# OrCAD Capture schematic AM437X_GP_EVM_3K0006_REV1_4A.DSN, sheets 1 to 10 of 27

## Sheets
1 Pg15: Camera #1: size C; title: AM437x General Purpose EVM; rev: 1.4A; company: Texas Instruments; note: am437x_gp_evm_3k0006_rev1_4a.dsn; note: ARM MPU BU; note: Final
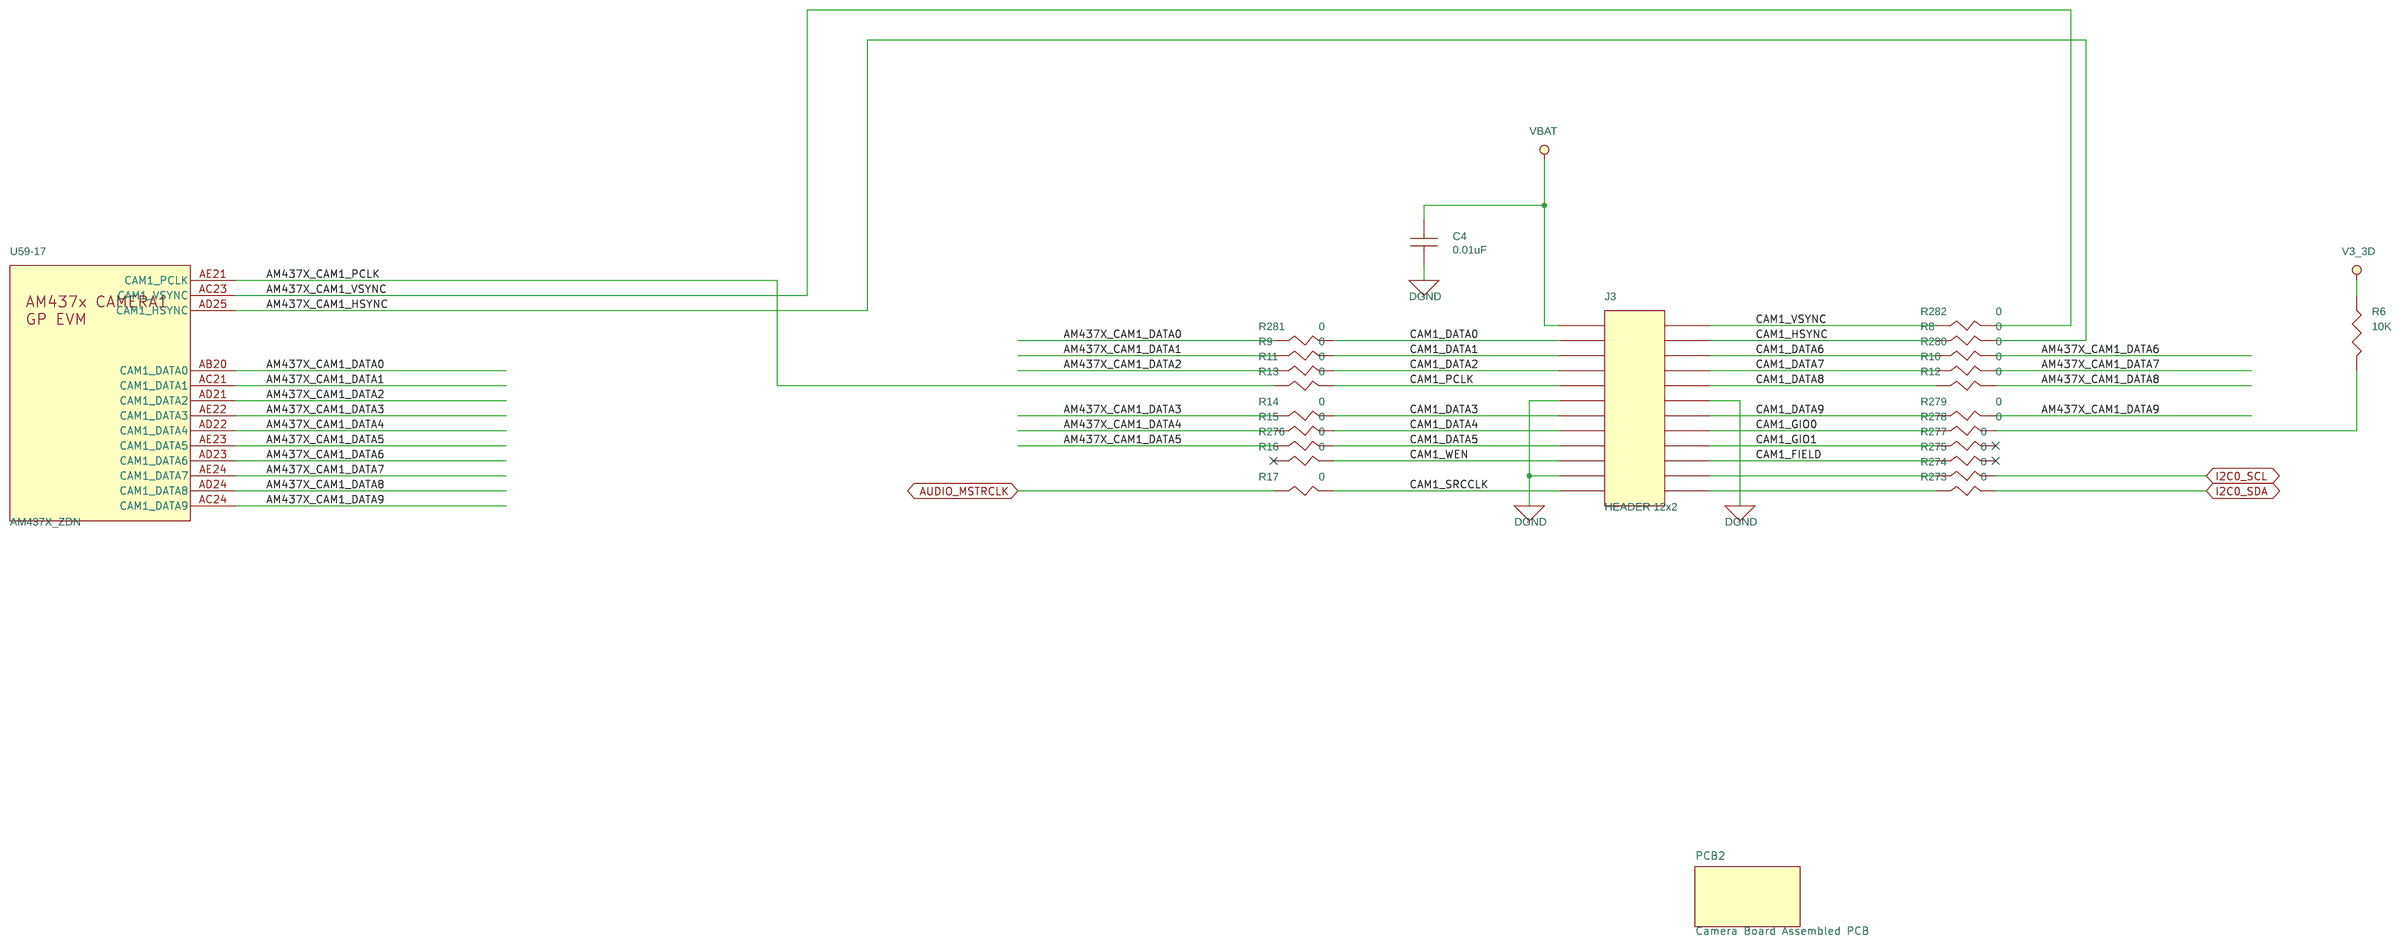
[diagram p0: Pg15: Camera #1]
2 Pg09: UART#0: size C
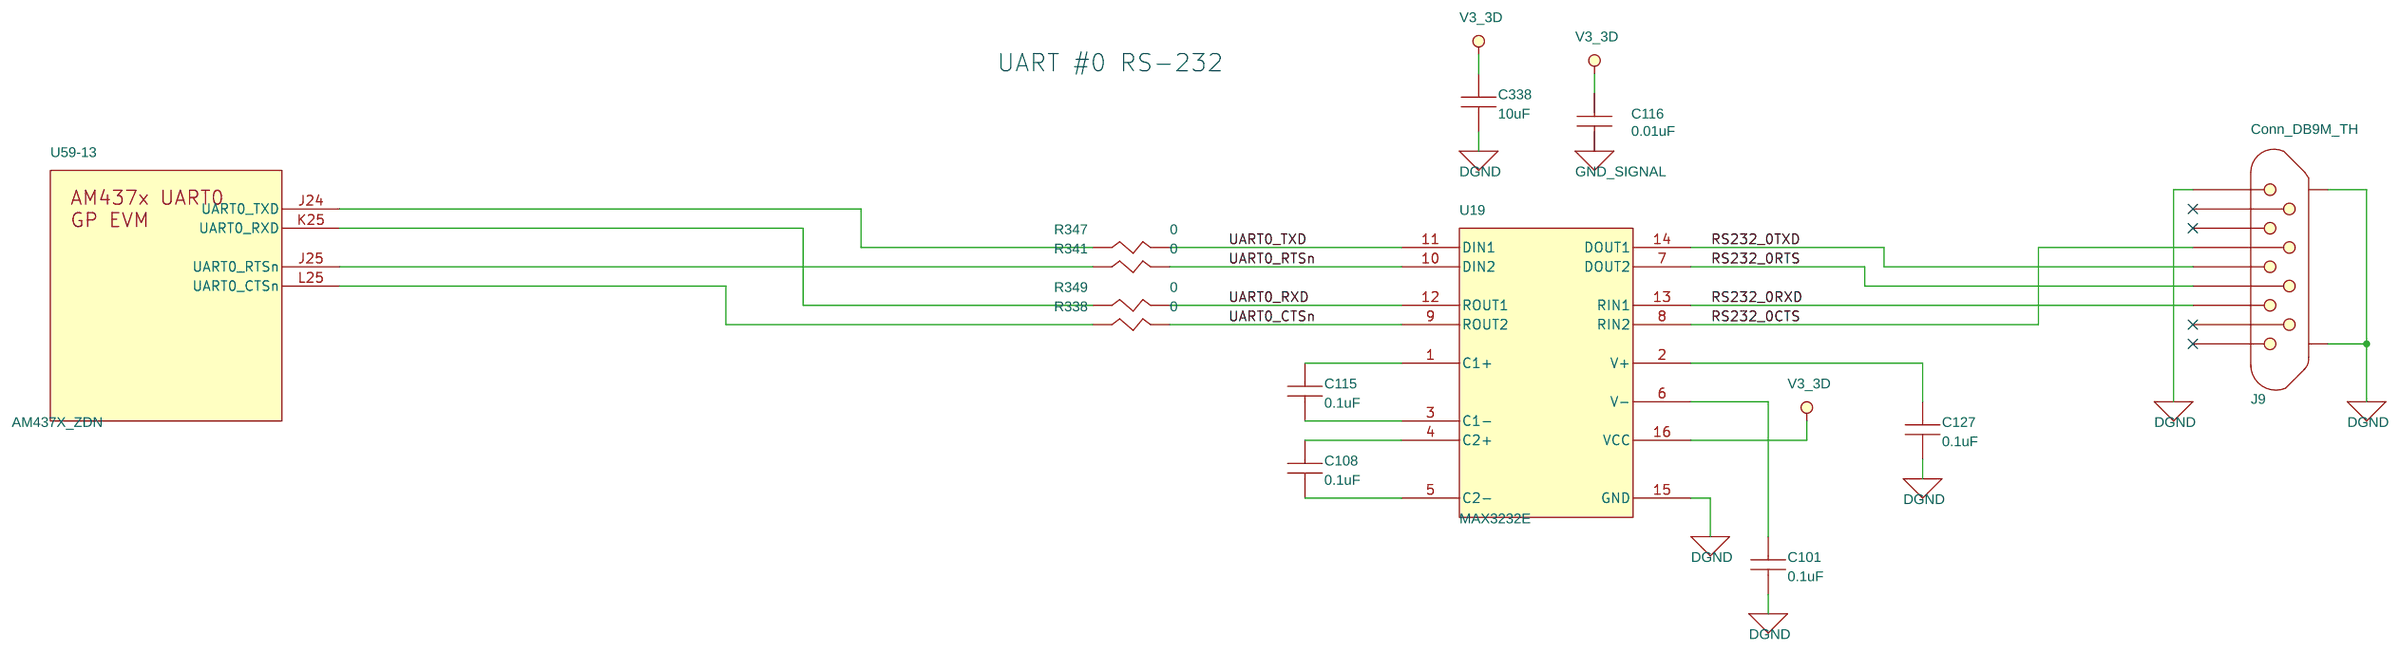
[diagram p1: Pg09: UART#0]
3 Pg13: HDMI: size C
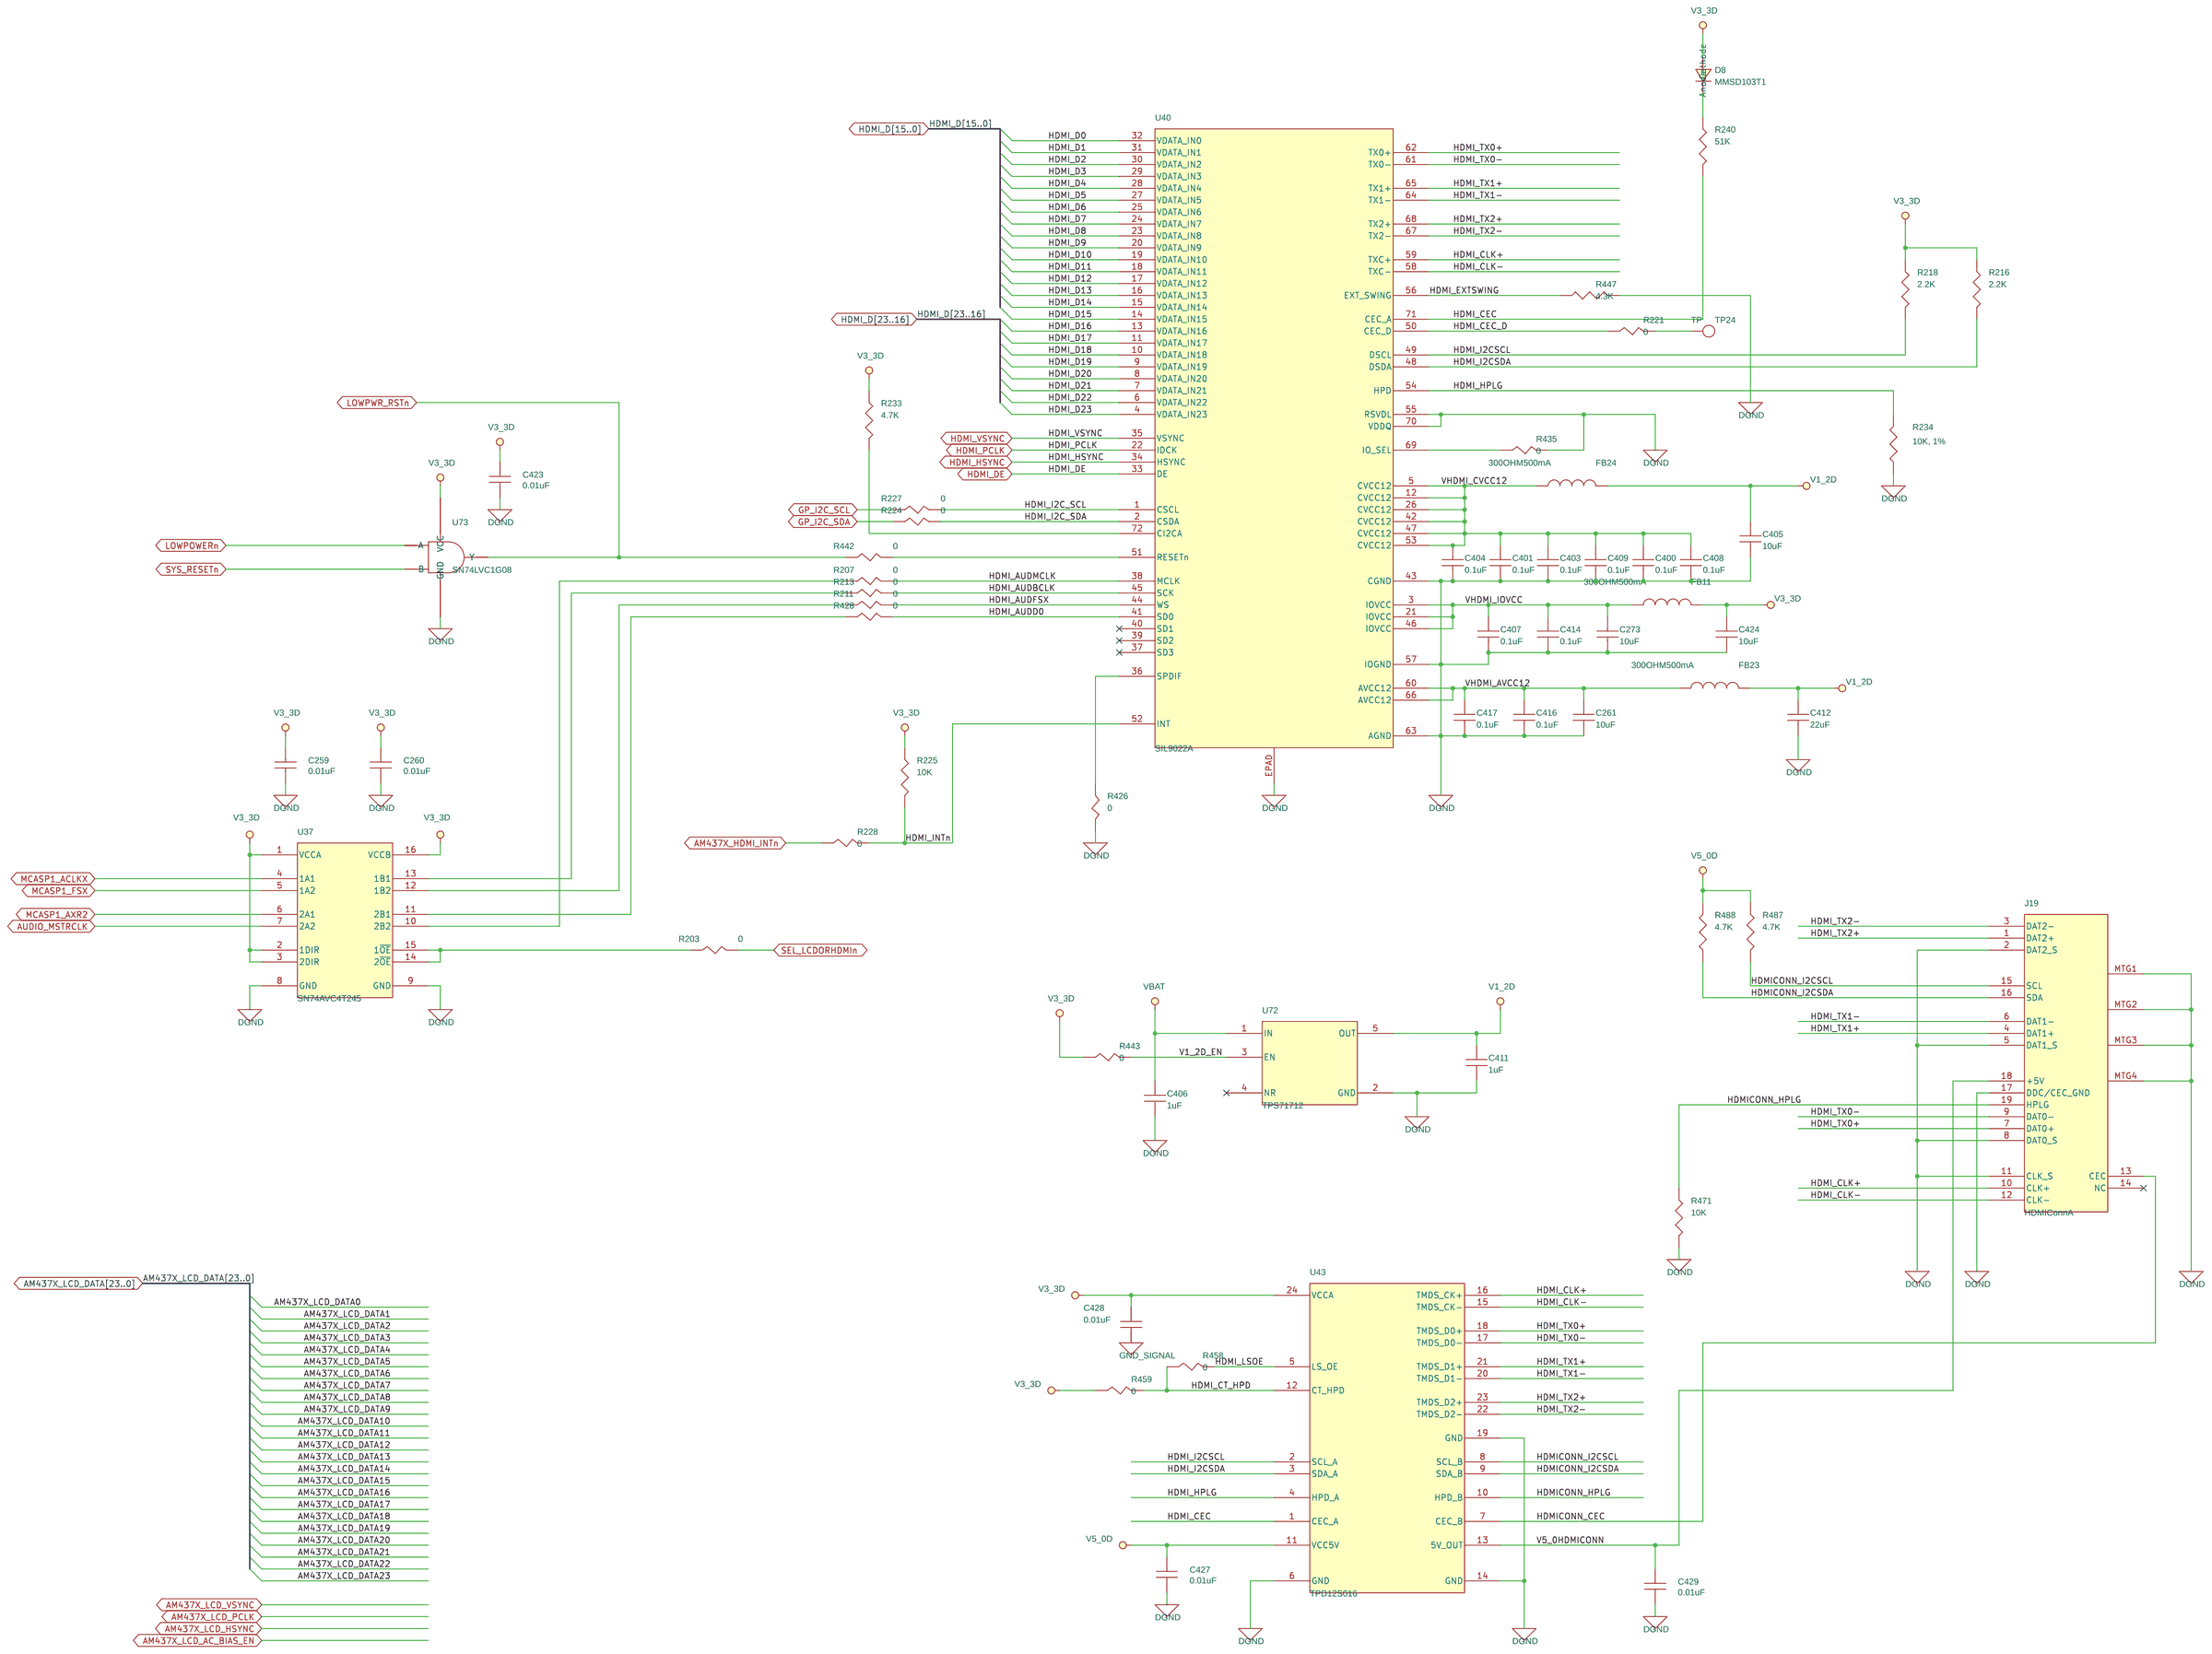
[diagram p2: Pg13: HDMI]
4 Pg16: ADC: size C
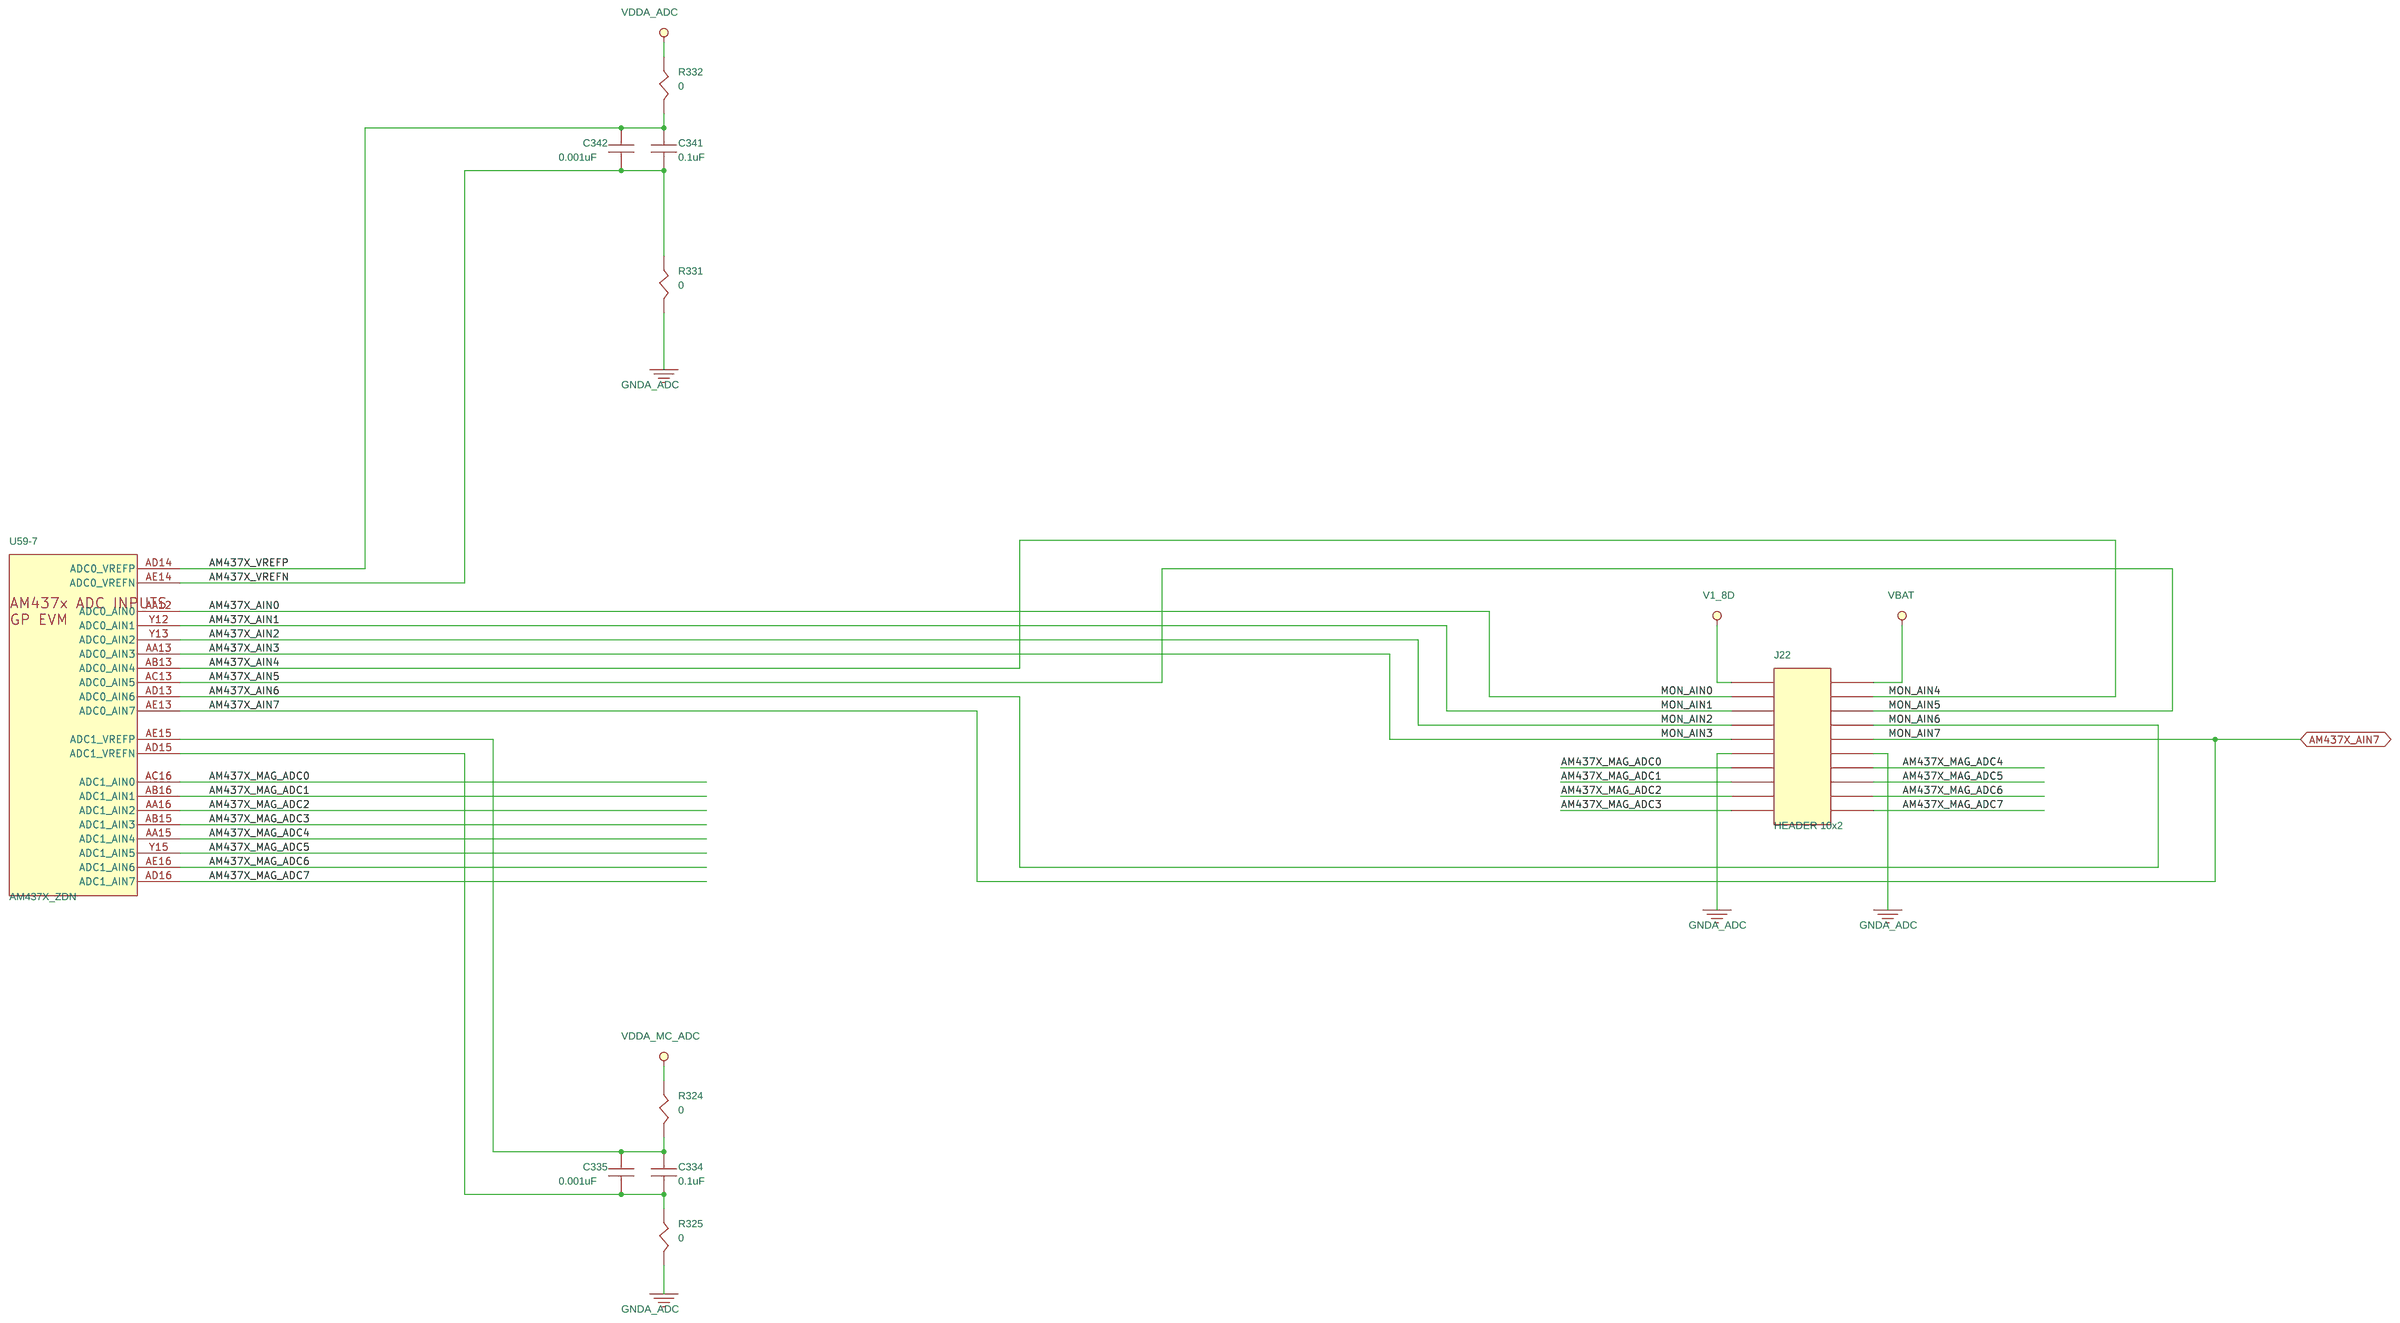
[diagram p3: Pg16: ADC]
5 Pg12: LCD: size C
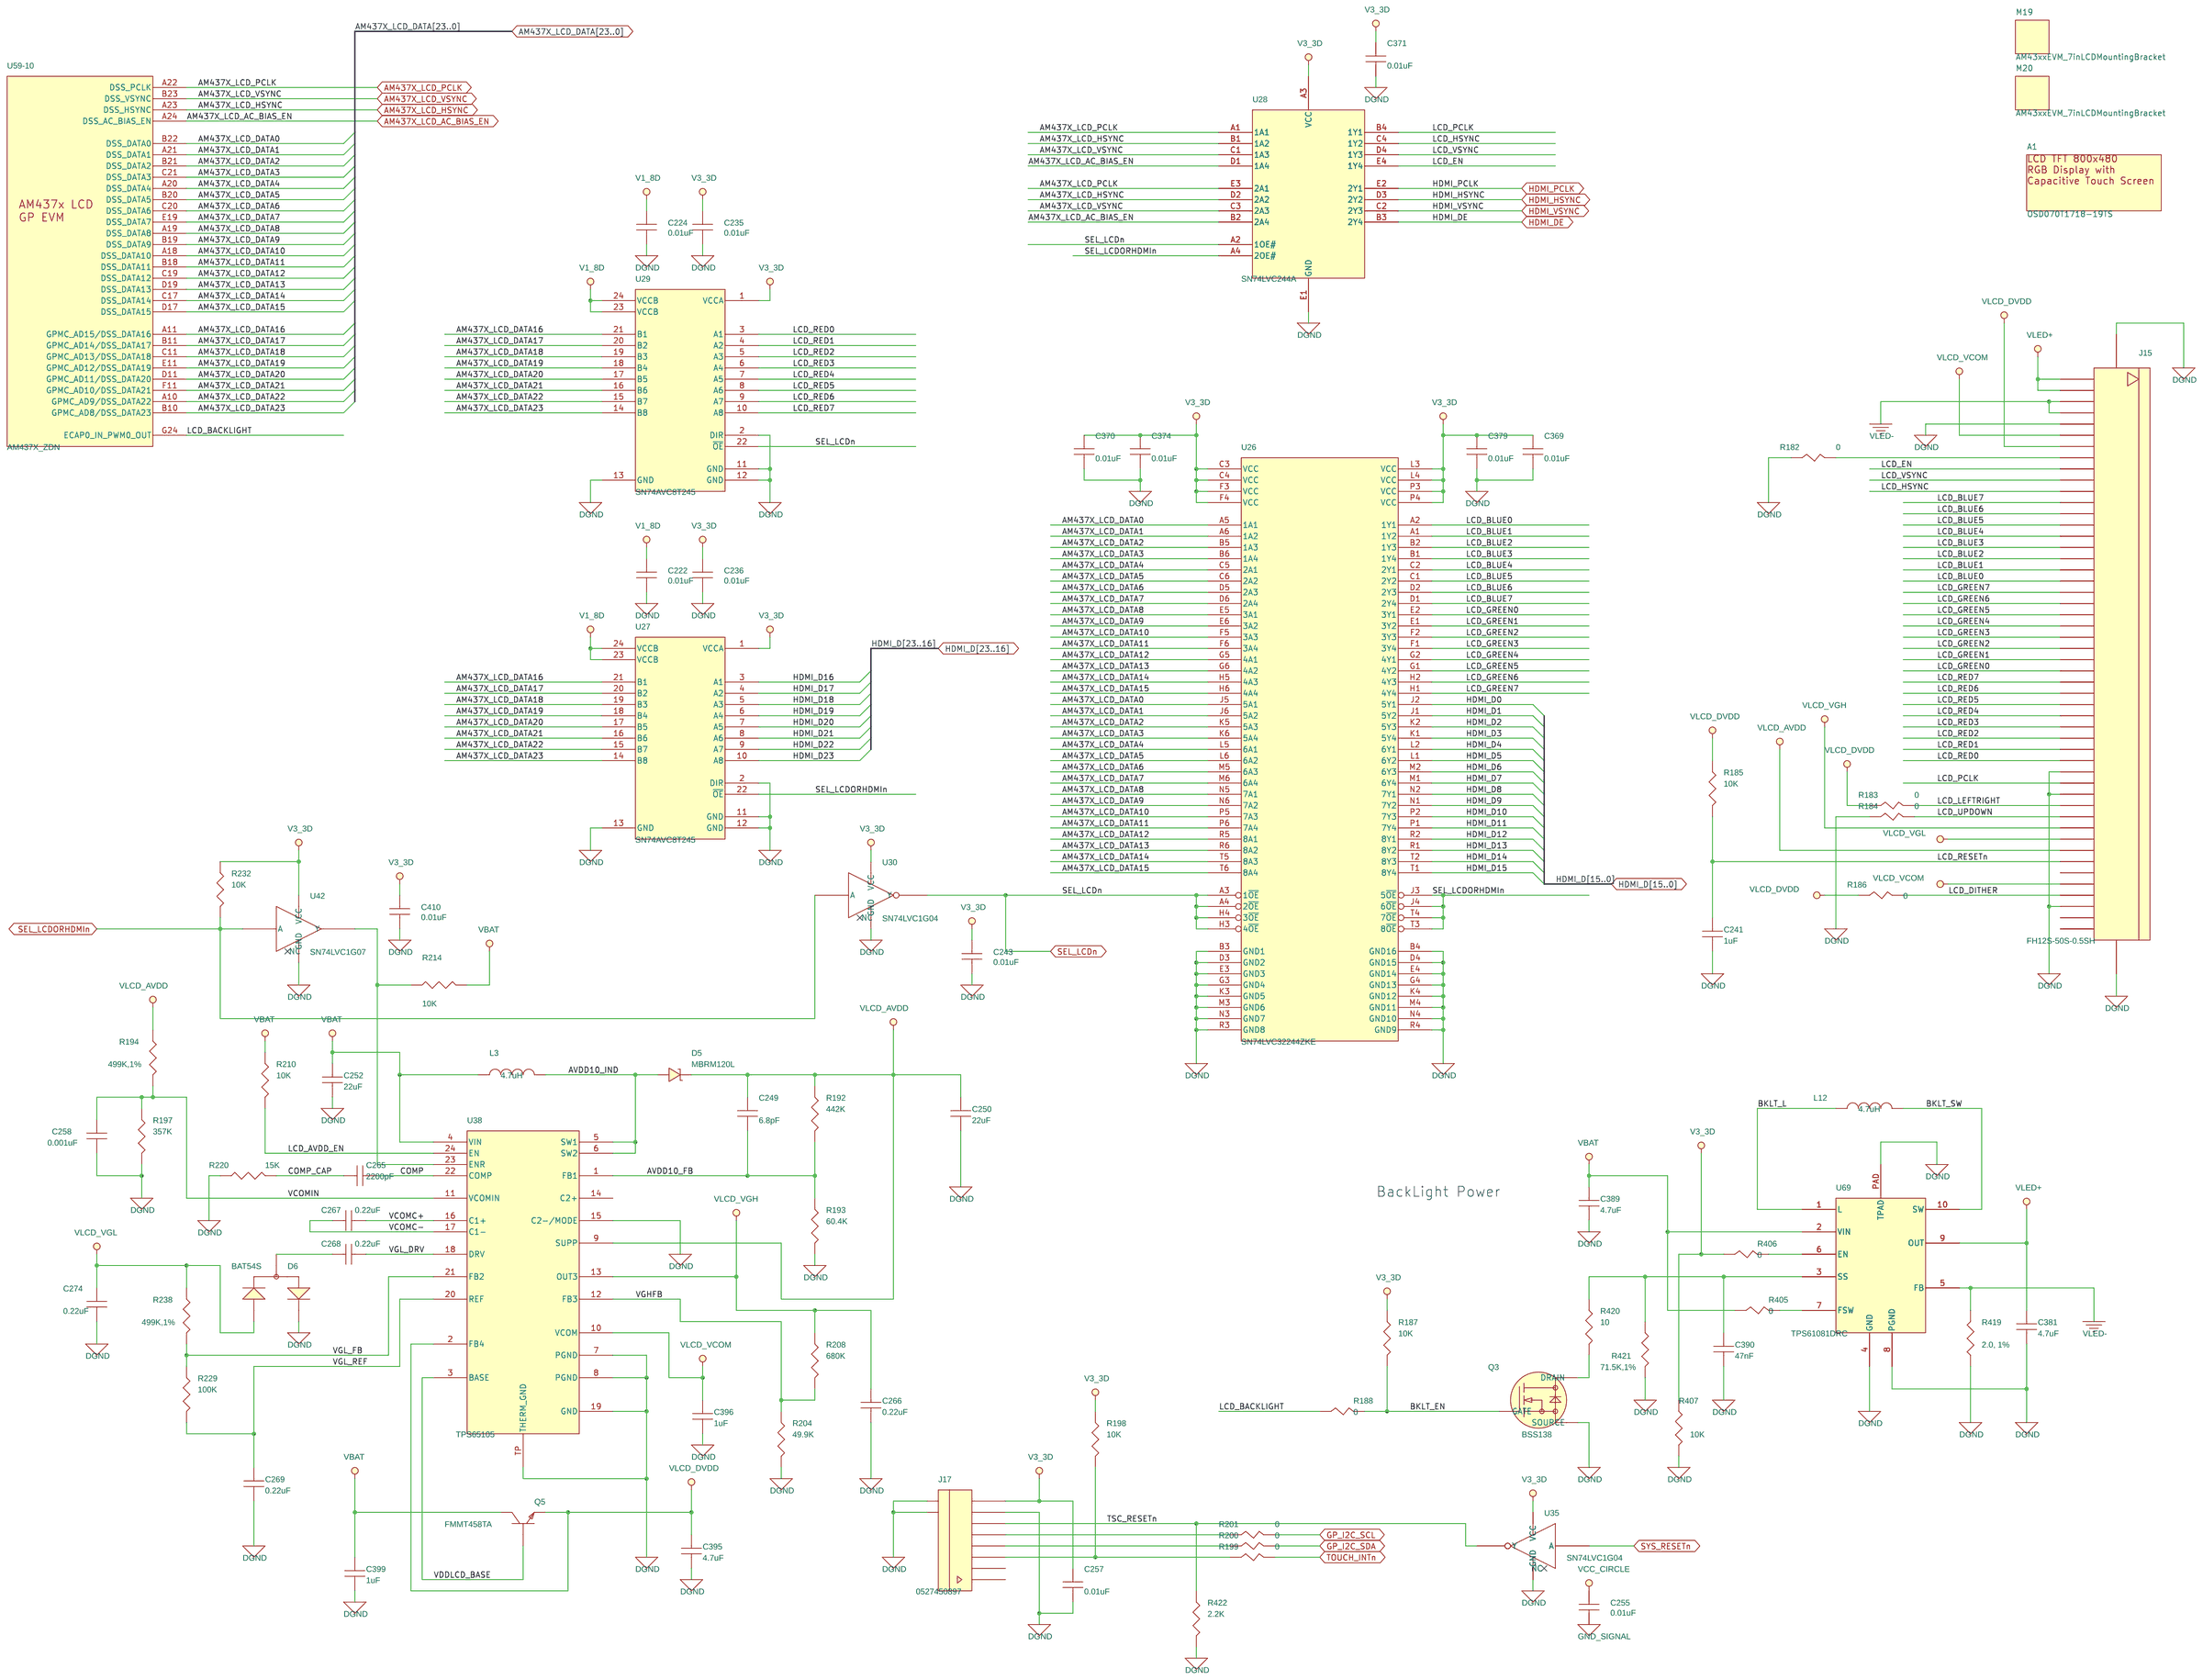
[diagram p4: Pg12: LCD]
6 Pg11: Audio: size C
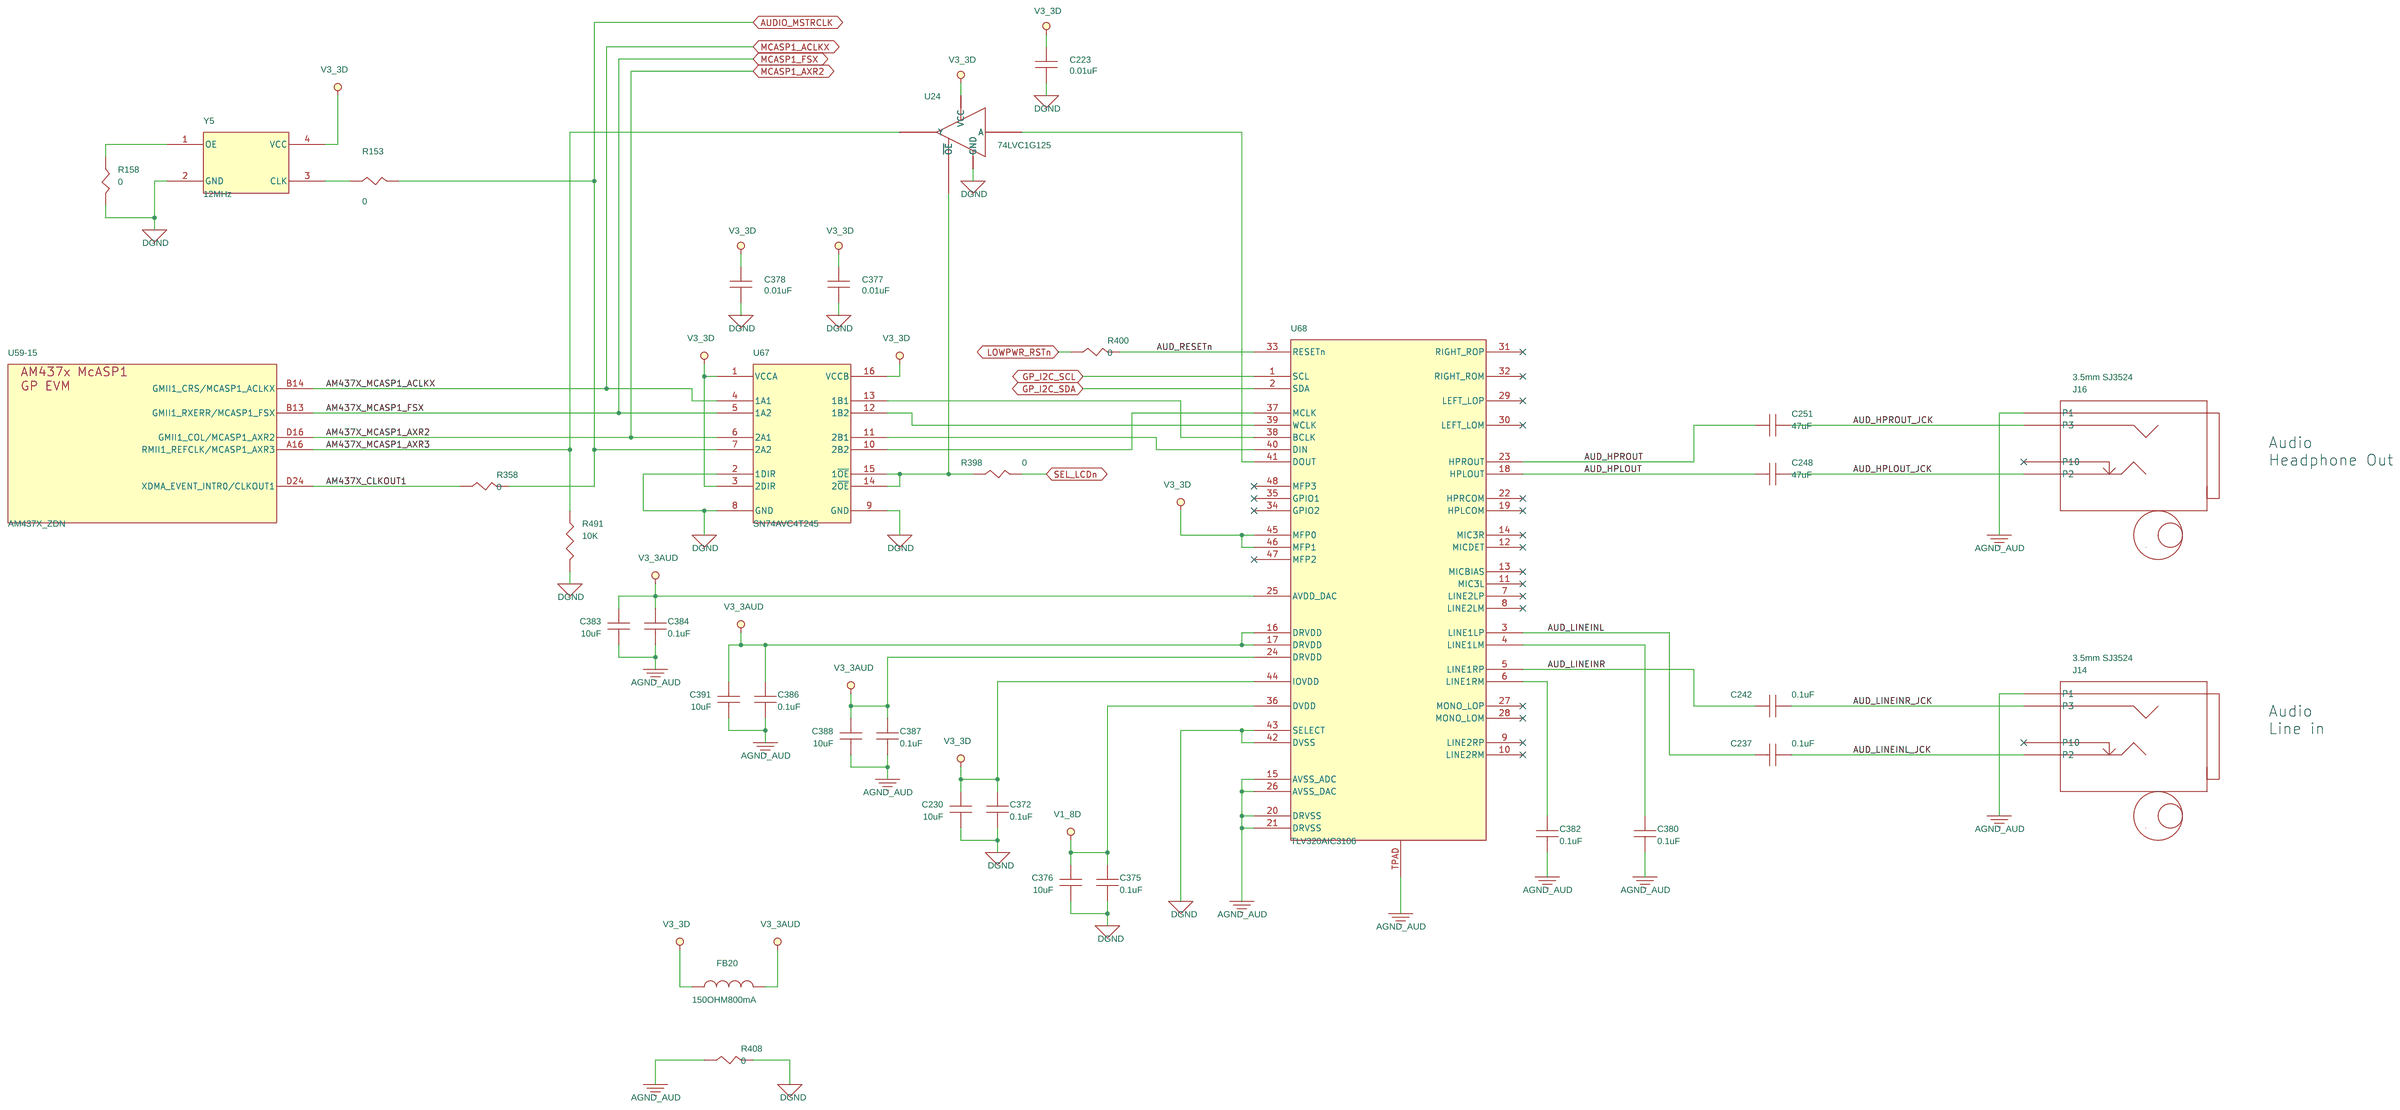
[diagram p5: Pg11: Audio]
7 Pg22: CAN #1: size C
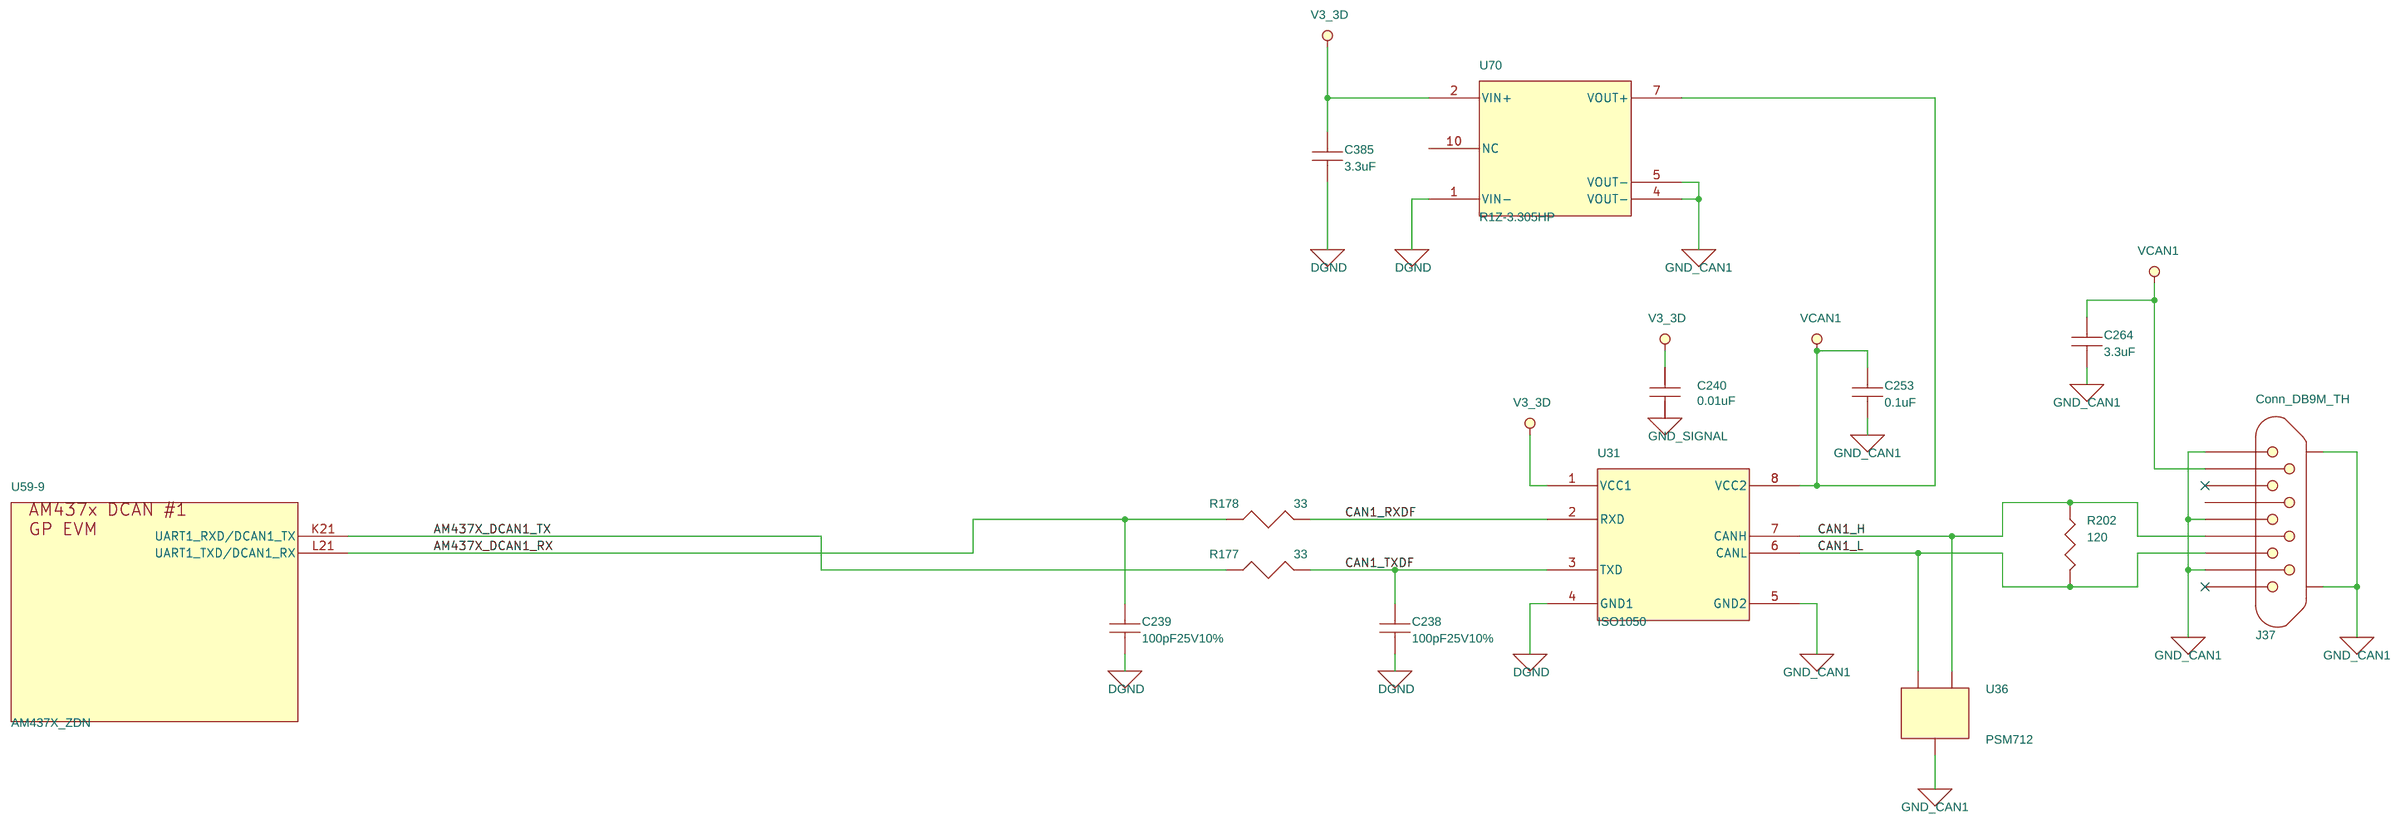
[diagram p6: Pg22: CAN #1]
8 Pg21: CAN #0: size C
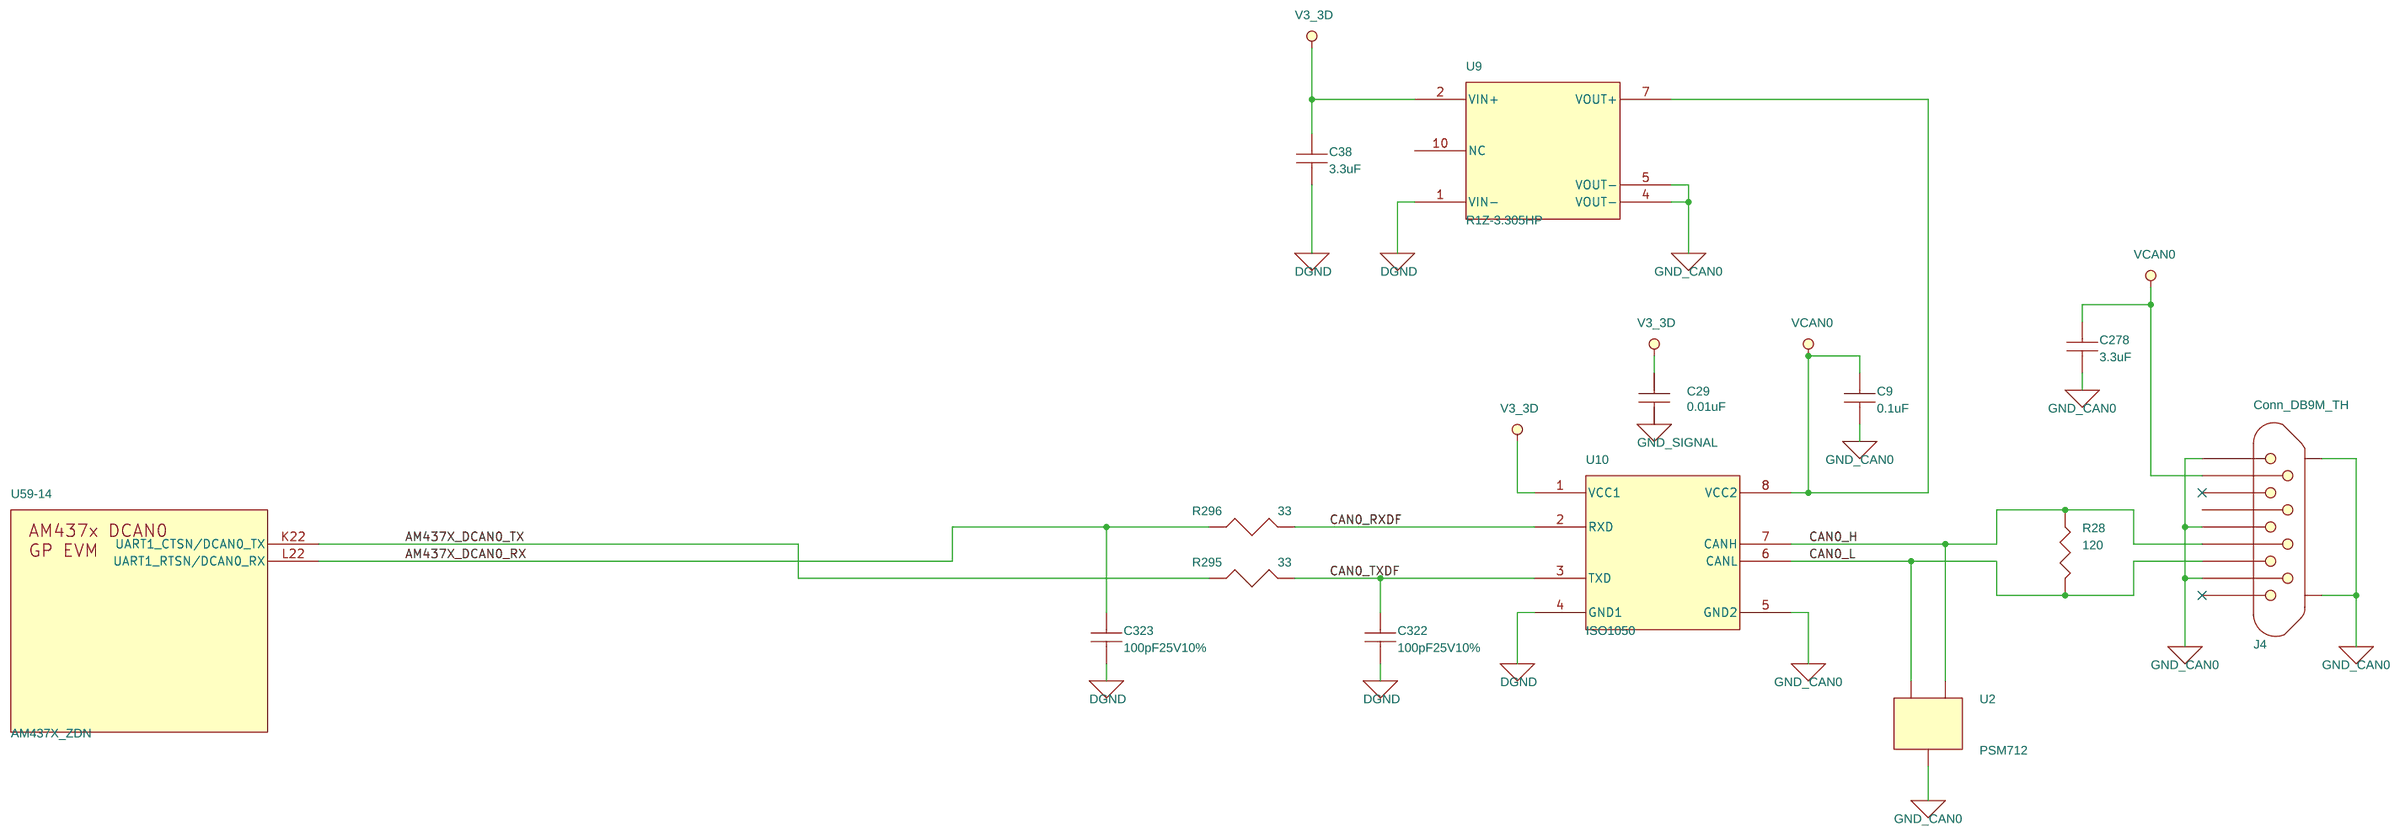
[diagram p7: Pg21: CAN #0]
9 Pg14: Camera #0: size C
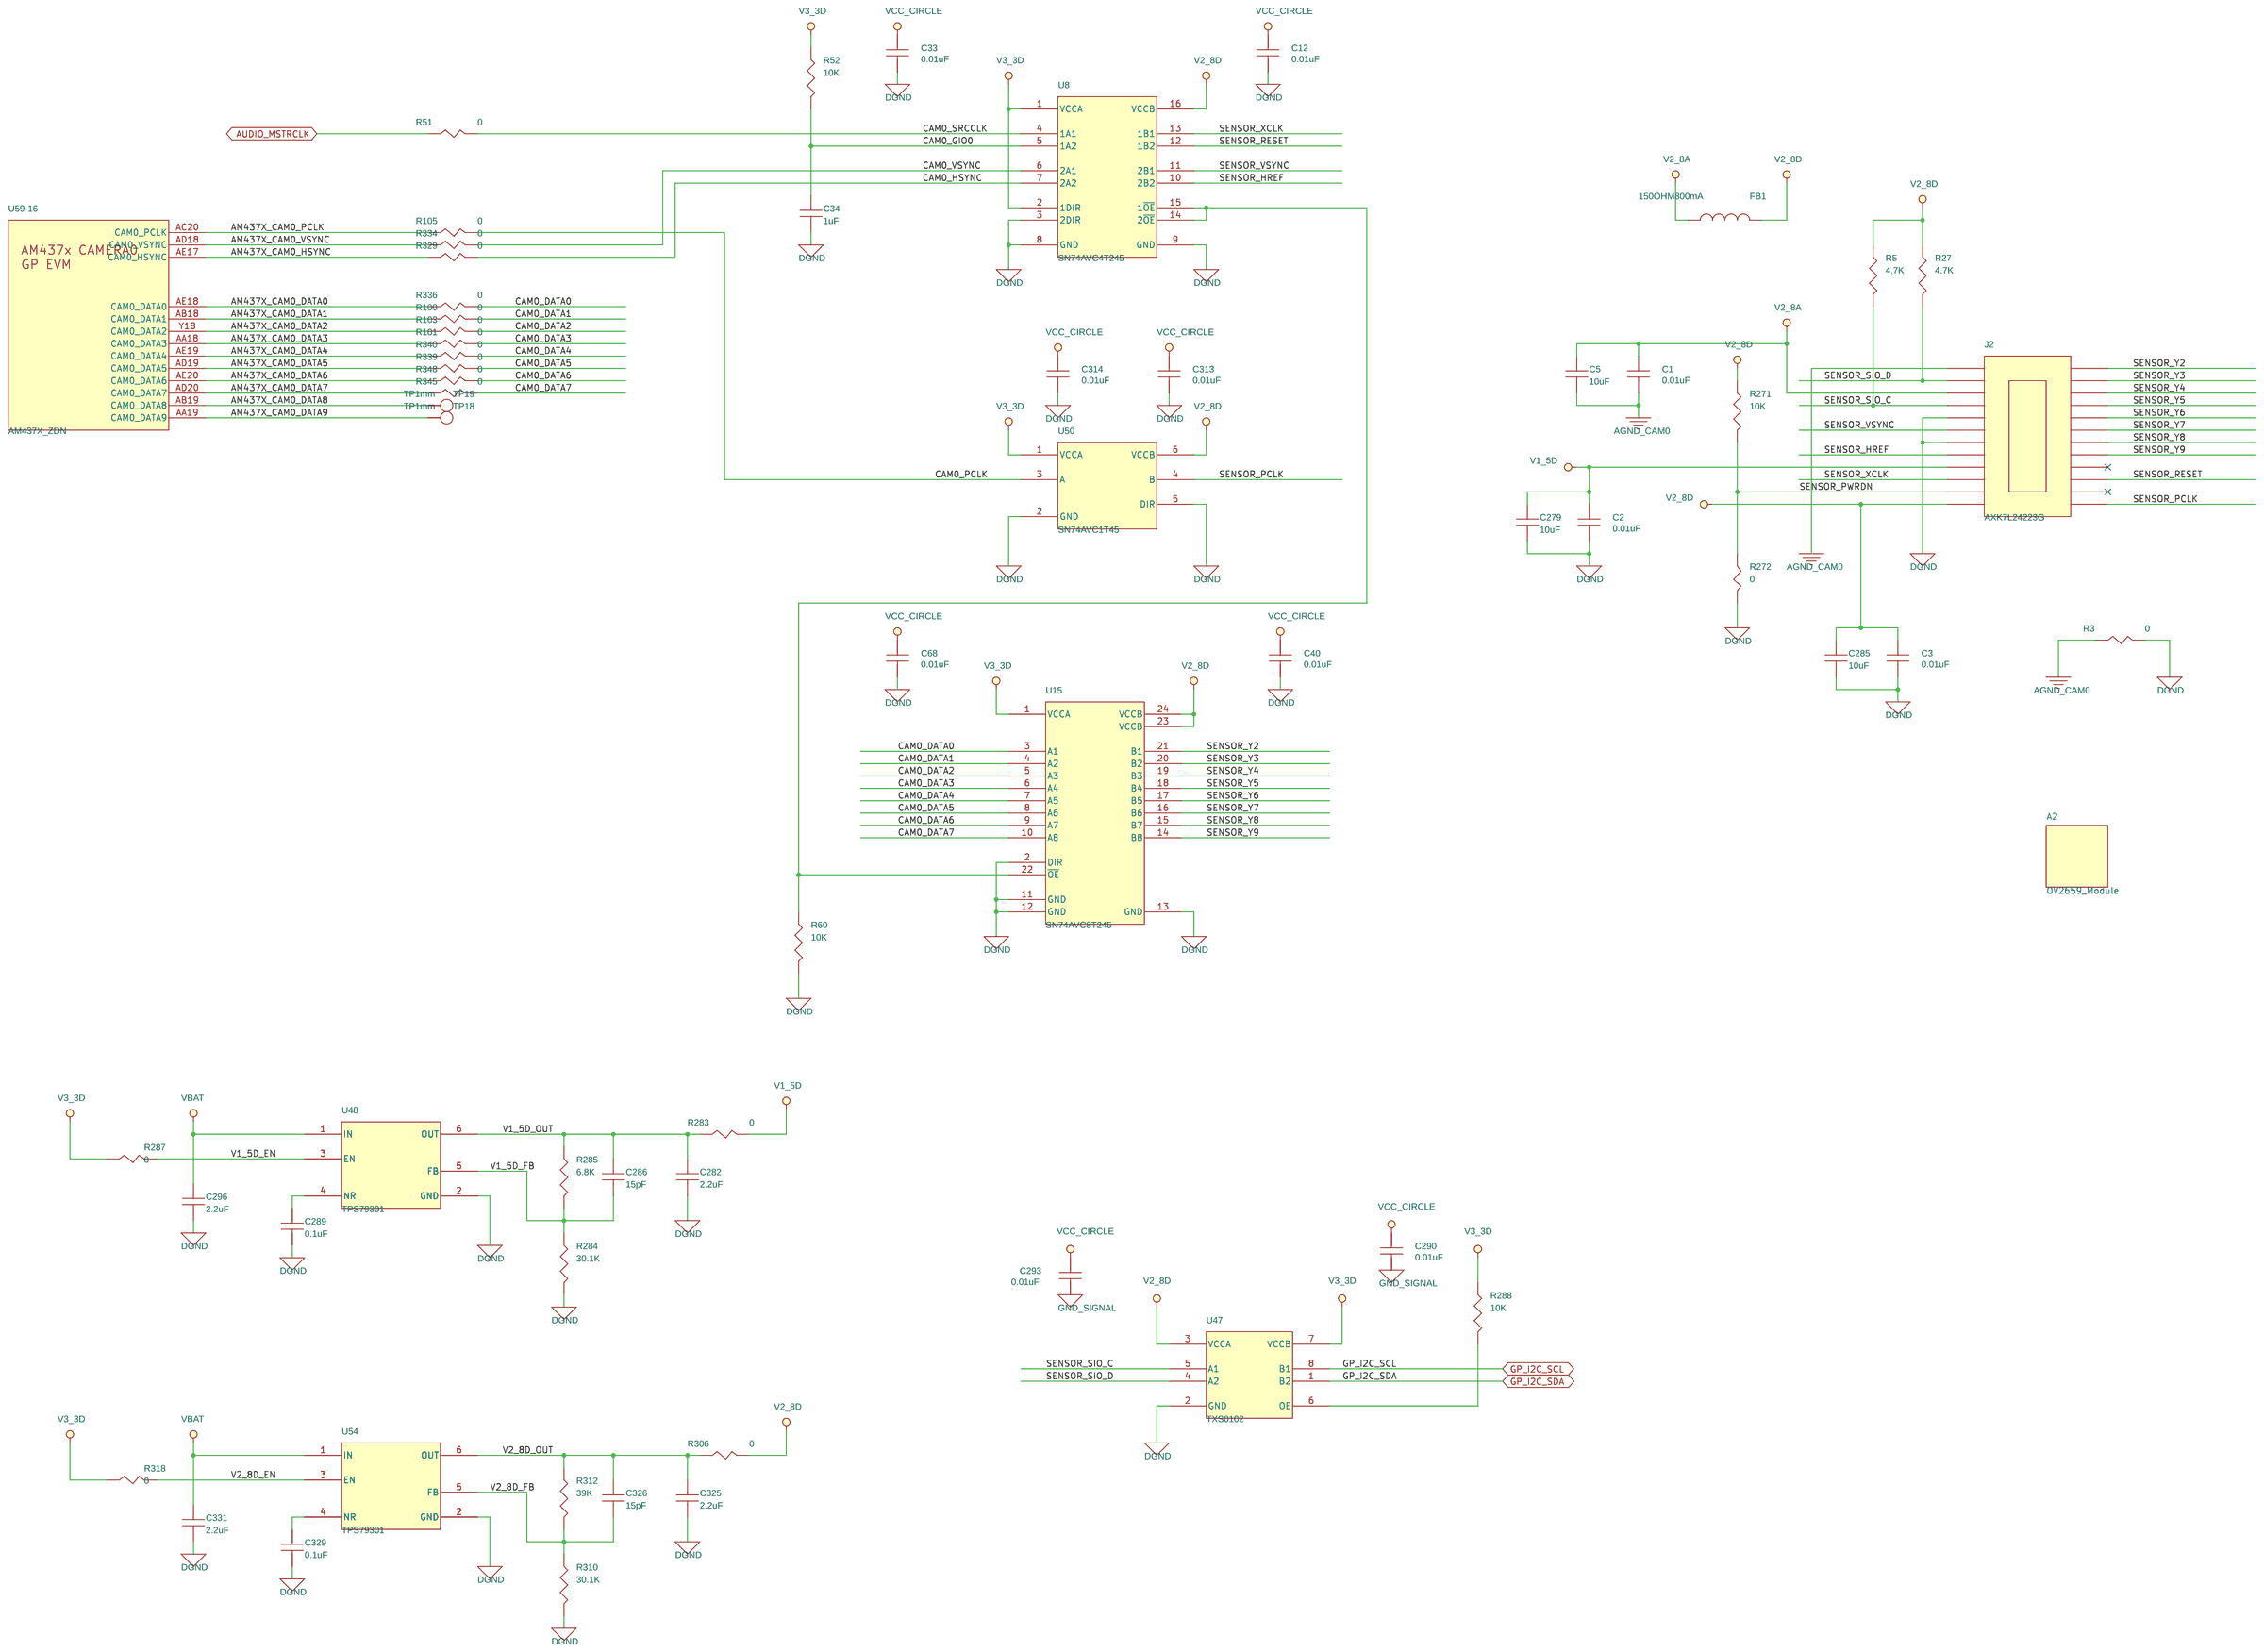
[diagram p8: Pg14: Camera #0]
10 Pg26: USB JTAG: size C
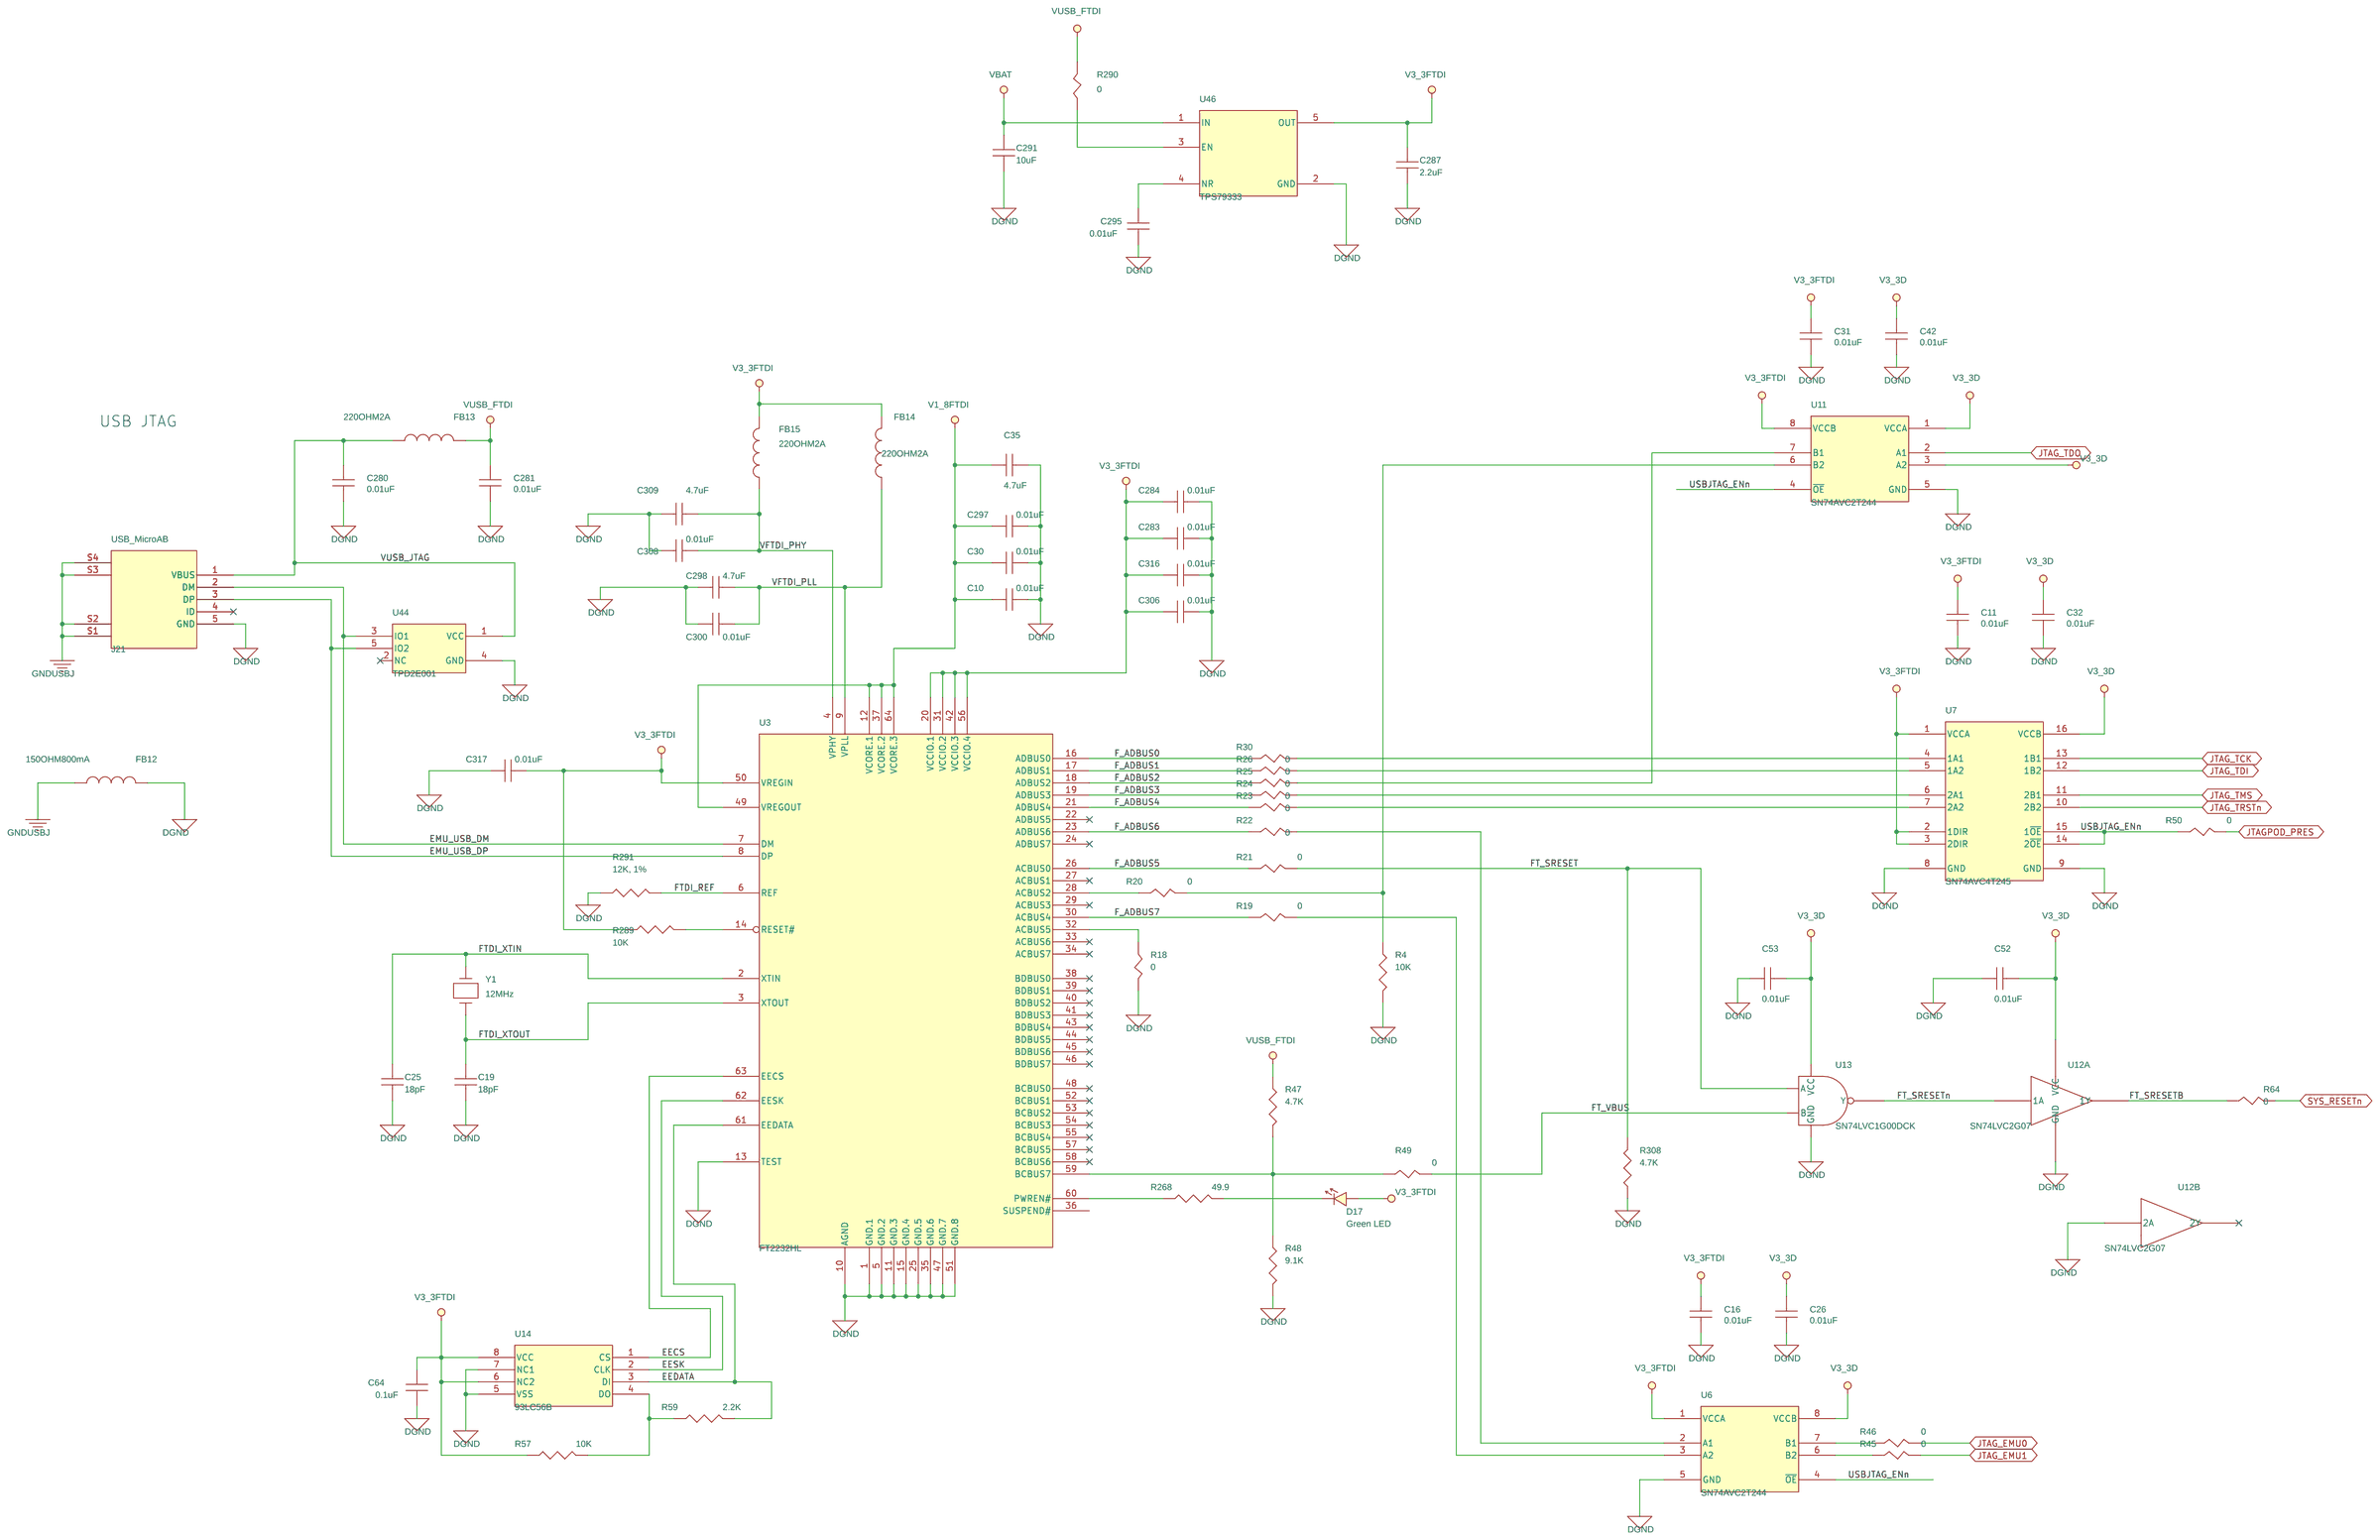
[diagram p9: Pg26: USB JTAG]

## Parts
sheet Pg09: UART#0
C101  0.1uF  [SM-7351-CAP-0402]
C108  0.1uF  [SM-7351-CAP-0402]
C115  0.1uF  [SM-7351-CAP-0402]
C116  0.01uF  [SM-7351-CAP-0402]
C127  0.1uF  [SM-7351-CAP-0402]
C338  10uF  [SM-7351-CAP-0805]
J9  Conn_DB9M_TH  [norcomp_db9m_th]
R338  0  [SM-7351-RES-0402]
R341  0  [SM-7351-RES-0402]
R347  0  [SM-7351-RES-0402]
R349  0  [SM-7351-RES-0402]
U19  MAX3232E  [U_16_D]
sheet Pg11: Audio
C223  0.01uF  [SM-7351-CAP-0402]
C230  10uF  [SM-7351-CAP-0805]
C237  0.1uF  [SM-7351-CAP-0402]
C242  0.1uF  [SM-7351-CAP-0402]
C248  47uF  [SM-7351-CAP-1206]
C251  47uF  [SM-7351-CAP-1206]
C372  0.1uF  [SM-7351-CAP-0402]
C375  0.1uF  [SM-7351-CAP-0402]
C376  10uF  [SM-7351-CAP-0805]
C377  0.01uF  [SM-7351-CAP-0402]
C378  0.01uF  [SM-7351-CAP-0402]
C380  0.1uF  [SM-7351-CAP-0402]
C382  0.1uF  [SM-7351-CAP-0402]
C383  10uF  [SM-7351-CAP-0805]
C384  0.1uF  [SM-7351-CAP-0402]
C386  0.1uF  [SM-7351-CAP-0402]
C387  0.1uF  [SM-7351-CAP-0402]
C388  10uF  [SM-7351-CAP-0805]
C391  10uF  [SM-7351-CAP-0805]
FB20  150OHM800mA  [sm-7351-ind-0805]
J14  3.5mm SJ3524  [sj3524smt4pin]
J16  3.5mm SJ3524  [sj3524smt4pin]
R153  0  [SM-7351-RES-0402]
R158  0  [SM-7351-RES-0402]
R358  0  [SM-7351-RES-0402]
R398  0  [SM-7351-RES-0402]
R400  0  [SM-7351-RES-0402]
R408  0  [SM-7351-RES-0603]
R491  10K  [SM-7351-RES-0402]
U24  74LVC1G125  [SC70-5-43M]
U67  SN74AVC4T245  [U_16_PW]
U68  TLV320AIC3106  [vqfn48_rgz]
Y5  12MHz  [ecs_smd3_2x5mm]
sheet Pg12: LCD
A1  OSD070T1718-19TS  [DNP]
C222  0.01uF  [SM-7351-CAP-0402]
C224  0.01uF  [SM-7351-CAP-0402]
C235  0.01uF  [SM-7351-CAP-0402]
C236  0.01uF  [SM-7351-CAP-0402]
C241  1uF  [SM-7351-CAP-0402]
C243  0.01uF  [SM-7351-CAP-0402]
C249  6.8pF  [SM-7351-CAP-0402]
C250  22uF  [SM-7351-CAP-0805]
C252  22uF  [SM-7351-CAP-0805]
C255  0.01uF  [SM-7351-CAP-0402]
C257  0.01uF  [SM-7351-CAP-0402]
C258  0.001uF  [SM-7351-CAP-0402]
C265  2200pF  [SM-7351-CAP-0402]
C266  0.22uF  [SM-7351-CAP-0603]
C267  0.22uF  [SM-7351-CAP-0603]
C268  0.22uF  [SM-7351-CAP-0603]
C269  0.22uF  [SM-7351-CAP-0603]
C274  0.22uF  [SM-7351-CAP-0603]
C369  0.01uF  [SM-7351-CAP-0402]
C370  0.01uF  [SM-7351-CAP-0402]
C371  0.01uF  [SM-7351-CAP-0402]
C374  0.01uF  [SM-7351-CAP-0402]
C379  0.01uF  [SM-7351-CAP-0402]
C381  4.7uF  [SM-7351-CAP-0805]
C389  4.7uF  [SM-7351-CAP-0603]
C390  47nF  [SM-7351-CAP-0402]
C395  4.7uF  [SM-7351-CAP-0603]
C396  1uF  [SM-7351-CAP-0402]
C399  1uF  [SM-7351-CAP-0402]
C410  0.01uF  [SM-7351-CAP-0402]
D5  MBRM120L  [SM_DIO_CASE_457-04]
D6  BAT54S  [SM_SOT323-3]
J15  FH12S-50S-0.5SH  [cnfh12s-50s-05sh]
J17  0527450897  [CN527450-897]
L3  4.7uH  [sm_ind_lqh32cn]
L12  4.7uH  [vlcf5020t]
M19  AM43xxEVM_7inLCDMountingBracket  [DNP]
M20  AM43xxEVM_7inLCDMountingBracket  [DNP]
Q3  BSS138  [SOT23-3]
Q5  FMMT458TA  [sm_sot23_bce]
R182  0  [SM-7351-RES-0402]
R183  0  [SM-7351-RES-0402]
R184  0  [SM-7351-RES-0402]
R185  10K  [SM-7351-RES-0402]
R186  0  [SM-7351-RES-0402]
R187  10K  [SM-7351-RES-0402]
R188  0  [SM-7351-RES-0402]
R192  442K  [SM-7351-RES-0402]
R193  60.4K  [SM-7351-RES-0402]
R194  499K,1%  [SM-7351-RES-0402]
R197  357K  [SM-7351-RES-0402]
R198  10K  [SM-7351-RES-0402]
R199  0  [SM-7351-RES-0402]
R200  0  [SM-7351-RES-0402]
R201  0  [SM-7351-RES-0402]
R204  49.9K  [SM-7351-RES-0402]
R208  680K  [SM-7351-RES-0402]
R210  10K  [SM-7351-RES-0402]
R214  10K  [SM-7351-RES-0402]
R220  15K  [SM-7351-RES-0402]
R229  100K  [SM-7351-RES-0402]
R232  10K  [SM-7351-RES-0402]
R238  499K,1%  [SM-7351-RES-0402]
R405  0  [SM-7351-RES-0402]
R406  0  [SM-7351-RES-0402]
R407  10K  [SM-7351-RES-0402]
R419  2.0, 1%  [SM-7351-RES-0603]
R420  10  [SM-7351-RES-0402]
R421  71.5K,1%  [SM-7351-RES-0402]
R422  2.2K  [sm-7351-res-0402]
U26  SN74LVC32244ZKE  [bga13x5-96]
U27  SN74AVC8T245  [TSSOP8x4-24-47m]
U28  SN74LVC244A  [bga3x4-20-39m]
U29  SN74AVC8T245  [TSSOP8x4-24-47m]
U30  SN74LVC1G04  [SC70-5-43M]
U35  SN74LVC1G04  [SC70-5-43M]
U38  TPS65105  [u_24_pw]
U42  SN74LVC1G07  [SC70-5-43M]
U69  TPS61081DRC  [u_10_drc]
sheet Pg13: HDMI
C259  0.01uF  [SM-7351-CAP-0402]
C260  0.01uF  [SM-7351-CAP-0402]
C261  10uF  [SM-7351-CAP-0805]
C273  10uF  [SM-7351-CAP-0805]
C400  0.1uF  [SM-7351-CAP-0402]
C401  0.1uF  [SM-7351-CAP-0402]
C403  0.1uF  [SM-7351-CAP-0402]
C404  0.1uF  [SM-7351-CAP-0402]
C405  10uF  [SM-7351-CAP-0805]
C406  1uF  [SM-7351-CAP-0402]
C407  0.1uF  [SM-7351-CAP-0402]
C408  0.1uF  [SM-7351-CAP-0402]
C409  0.1uF  [SM-7351-CAP-0402]
C411  1uF  [SM-7351-CAP-0402]
C412  22uF  [SM-7351-CAP-0805]
C414  0.1uF  [SM-7351-CAP-0402]
C416  0.1uF  [SM-7351-CAP-0402]
C417  0.1uF  [SM-7351-CAP-0402]
C423  0.01uF  [SM-7351-CAP-0402]
C424  10uF  [SM-7351-CAP-0805]
C427  0.01uF  [SM-7351-CAP-0402]
C428  0.01uF  [SM-7351-CAP-0402]
C429  0.01uF  [SM-7351-CAP-0402]
D8  MMSD103T1  [sod-123]
FB11  300OHM500mA  [sm-7351-ind-0603]
FB23  300OHM500mA  [sm-7351-ind-0603]
FB24  300OHM500mA  [sm-7351-ind-0603]
J19  HDMIConnA  [smd_hdmia_ra]
R203  0  [SM-7351-RES-0402]
R207  0  [SM-7351-RES-0402]
R211  0  [SM-7351-RES-0402]
R213  0  [SM-7351-RES-0402]
R216  2.2K  [sm-7351-res-0402]
R218  2.2K  [sm-7351-res-0402]
R221  0  [SM-7351-RES-0402]
R224  0  [SM-7351-RES-0402]
R225  10K  [SM-7351-RES-0402]
R227  0  [SM-7351-RES-0402]
R228  0  [SM-7351-RES-0402]
R233  4.7K  [SM-7351-RES-0402]
R234  10K, 1%  [SM-7351-RES-0402]
R240  51K  [SM-7351-RES-0402]
R426  0  [SM-7351-RES-0402]
R428  0  [SM-7351-RES-0402]
R435  0  [SM-7351-RES-0402]
R442  0  [SM-7351-RES-0402]
R443  0  [SM-7351-RES-0402]
R447  4.3K  [SM-7351-RES-0402]
R458  0  [SM-7351-RES-0402]
R459  0  [SM-7351-RES-0402]
R471  10K  [SM-7351-RES-0402]
R487  4.7K  [SM-7351-RES-0402]
R488  4.7K  [SM-7351-RES-0402]
TP24  TP  [TH_TP_5002]
U37  SN74AVC4T245  [U_16_PW]
U40  SIL9022A  [QFN_72]
U43  TPD12S016  [pw_24pin_tssop]
U72  TPS71712  [smdsc70-5]
U73  SN74LVC1G08  [sm-so-sc70-5]
sheet Pg14: Camera #0
A2  OV2659_Module  [DNP]
C1  0.01uF  [SM-7351-CAP-0402]
C2  0.01uF  [SM-7351-CAP-0402]
C3  0.01uF  [SM-7351-CAP-0402]
C5  10uF  [SM-7351-CAP-0805]
C12  0.01uF  [SM-7351-CAP-0402]
C33  0.01uF  [SM-7351-CAP-0402]
C34  1uF  [SM-7351-CAP-0402]
C40  0.01uF  [SM-7351-CAP-0402]
C68  0.01uF  [SM-7351-CAP-0402]
C279  10uF  [SM-7351-CAP-0805]
C282  2.2uF  [SM-7351-CAP-0603]
C285  10uF  [SM-7351-CAP-0805]
C286  15pF  [SM-7351-CAP-0402]
C289  0.1uF  [SM-7351-CAP-0402]
C290  0.01uF  [SM-7351-CAP-0402]
C293  0.01uF  [SM-7351-CAP-0402]
C296  2.2uF  [SM-7351-CAP-0603]
C313  0.01uF  [SM-7351-CAP-0402]
C314  0.01uF  [SM-7351-CAP-0402]
C325  2.2uF  [SM-7351-CAP-0603]
C326  15pF  [SM-7351-CAP-0402]
C329  0.1uF  [SM-7351-CAP-0402]
C331  2.2uF  [SM-7351-CAP-0603]
FB1  150OHM800mA  [sm-7351-ind-0805]
J2  AXK7L24223G  [SCKAXK7L24]
R3  0  [SM-7351-RES-0603]
R5  4.7K  [SM-7351-RES-0402]
R27  4.7K  [SM-7351-RES-0402]
R51  0  [SM-7351-RES-0402]
R52  10K  [SM-7351-RES-0402]
R60  10K  [SM-7351-RES-0402]
R100  0  [SM-7351-RES-0402]
R101  0  [SM-7351-RES-0402]
R103  0  [SM-7351-RES-0402]
R105  0  [SM-7351-RES-0402]
R271  10K  [SM-7351-RES-0402]
R272  0  [SM-7351-RES-0402]
R283  0  [SM-7351-RES-0603]
R284  30.1K  [SM-7351-RES-0402]
R285  6.8K  [SM-7351-RES-0402]
R287  0  [SM-7351-RES-0402]
R288  10K  [SM-7351-RES-0402]
R306  0  [SM-7351-RES-0603]
R310  30.1K  [SM-7351-RES-0402]
R312  39K  [SM-7351-RES-0402]
R318  0  [SM-7351-RES-0402]
R329  0  [SM-7351-RES-0402]
R334  0  [SM-7351-RES-0402]
R336  0  [SM-7351-RES-0402]
R339  0  [SM-7351-RES-0402]
R340  0  [SM-7351-RES-0402]
R345  0  [SM-7351-RES-0402]
R348  0  [SM-7351-RES-0402]
TP18  TP1mm  [tp_smd1mmcircle]
TP19  TP1mm  [tp_smd1mmcircle]
U8  SN74AVC4T245  [U_16_PW]
U15  SN74AVC8T245  [TSSOP8x4-24-47m]
U47  TXS0102  [dct8]
U48  TPS79301  [U_6_DBV]
U50  SN74AVC1T45  [smdsc70-6]
U54  TPS79301  [U_6_DBV]
sheet Pg15: Camera #1
C4  0.01uF  [SM-7351-CAP-0402]
J3  HEADER 12x2  [hdr2x12]
PCB2  Camera Board Assembled PCB  [DNP]
R6  10K  [SM-7351-RES-0402]
R8  0  [SM-7351-RES-0402]
R9  0  [SM-7351-RES-0402]
R10  0  [SM-7351-RES-0402]
R11  0  [SM-7351-RES-0402]
R12  0  [SM-7351-RES-0402]
R13  0  [SM-7351-RES-0402]
R14  0  [SM-7351-RES-0402]
R15  0  [SM-7351-RES-0402]
R16  0  [SM-7351-RES-0402]
R17  0  [SM-7351-RES-0402]
R273  0  [SM-7351-RES-0402]
R274  0  [SM-7351-RES-0402]
R275  0  [SM-7351-RES-0402]
R276  0  [SM-7351-RES-0402]
R277  0  [SM-7351-RES-0402]
R278  0  [SM-7351-RES-0402]
R279  0  [SM-7351-RES-0402]
R280  0  [SM-7351-RES-0402]
R281  0  [SM-7351-RES-0402]
R282  0  [SM-7351-RES-0402]
sheet Pg16: ADC
C334  0.1uF  [SM-7351-CAP-0402]
C335  0.001uF  [SM-7351-CAP-0402]
C341  0.1uF  [SM-7351-CAP-0402]
C342  0.001uF  [SM-7351-CAP-0402]
J22  HEADER 10x2  [HDR2X10-330M]
R324  0  [SM-7351-RES-0402]
R325  0  [SM-7351-RES-0402]
R331  0  [SM-7351-RES-0402]
R332  0  [SM-7351-RES-0402]
sheet Pg21: CAN #0
C9  0.1uF  [SM-7351-CAP-0402]
C29  0.01uF  [SM-7351-CAP-0402]
C38  3.3uF  [SM-7351-CAP-0603]
C278  3.3uF  [SM-7351-CAP-0603]
C322  100pF25V10%  [SM-7351-CAP-0402]
C323  100pF25V10%  [SM-7351-CAP-0402]
J4  Conn_DB9M_TH  [norcomp_db9m_th]
R28  120  [SM-7351-RES-0402]
R295  33  [SM-7351-RES-0402]
R296  33  [SM-7351-RES-0402]
U2  PSM712  [sm-sot-23]
U9  R1Z-3.305HP  [smd15x11-6-374m]
U10  ISO1050  [so9x6-8-191m]
sheet Pg22: CAN #1
C238  100pF25V10%  [SM-7351-CAP-0402]
C239  100pF25V10%  [SM-7351-CAP-0402]
C240  0.01uF  [SM-7351-CAP-0402]
C253  0.1uF  [SM-7351-CAP-0402]
C264  3.3uF  [SM-7351-CAP-0603]
C385  3.3uF  [SM-7351-CAP-0603]
J37  Conn_DB9M_TH  [norcomp_db9m_th]
R177  33  [SM-7351-RES-0402]
R178  33  [SM-7351-RES-0402]
R202  120  [SM-7351-RES-0402]
U31  ISO1050  [so9x6-8-191m]
U36  PSM712  [sm-sot-23]
U70  R1Z-3.305HP  [smd15x11-6-374m]
sheet Pg23: Unused pins/GPIO
U59  AM437X_ZDN  [AM437X_ZDN]  (sections -1,-10,-11,-12,-13,-14,-15,-16,-17,-18,-19,-2,-20,-21,-22,-23,-24,-25,-3,-4,-5,-6,-7,-8,-9)
sheet Pg26: USB JTAG
C10  0.01uF  [SM-7351-CAP-0402]
C11  0.01uF  [SM-7351-CAP-0402]
C16  0.01uF  [SM-7351-CAP-0402]
C19  18pF  [SM-7351-CAP-0402]
C25  18pF  [SM-7351-CAP-0402]
C26  0.01uF  [SM-7351-CAP-0402]
C30  0.01uF  [SM-7351-CAP-0402]
C31  0.01uF  [SM-7351-CAP-0402]
C32  0.01uF  [SM-7351-CAP-0402]
C35  4.7uF  [SM-7351-CAP-0603]
C42  0.01uF  [SM-7351-CAP-0402]
C52  0.01uF  [SM-7351-CAP-0402]
C53  0.01uF  [SM-7351-CAP-0402]
C64  0.1uF  [SM-7351-CAP-0402]
C280  0.01uF  [SM-7351-CAP-0402]
C281  0.01uF  [SM-7351-CAP-0402]
C283  0.01uF  [SM-7351-CAP-0402]
C284  0.01uF  [SM-7351-CAP-0402]
C287  2.2uF  [SM-7351-CAP-0805]
C291  10uF  [SM-7351-CAP-0805]
C295  0.01uF  [SM-7351-CAP-0402]
C297  0.01uF  [SM-7351-CAP-0402]
C298  4.7uF  [SM-7351-CAP-0603]
C300  0.01uF  [SM-7351-CAP-0402]
C306  0.01uF  [SM-7351-CAP-0402]
C308  0.01uF  [SM-7351-CAP-0402]
C309  4.7uF  [SM-7351-CAP-0603]
C316  0.01uF  [SM-7351-CAP-0402]
C317  0.01uF  [SM-7351-CAP-0402]
D17  Green LED  [sm_led_0805]
FB12  150OHM800mA  [sm-7351-ind-0805]
FB13  220OHM2A  [sm-7351-ind-0603]
FB14  220OHM2A  [sm-7351-ind-0603]
FB15  220OHM2A  [sm-7351-ind-0603]
J21  USB_MicroAB  [ZX62-AB-5PA]
R4  10K  [SM-7351-RES-0402]
R18  0  [SM-7351-RES-0402]
R19  0  [SM-7351-RES-0402]
R20  0  [SM-7351-RES-0402]
R21  0  [SM-7351-RES-0402]
R22  0  [SM-7351-RES-0402]
R23  0  [SM-7351-RES-0402]
R24  0  [SM-7351-RES-0402]
R25  0  [SM-7351-RES-0402]
R26  0  [SM-7351-RES-0402]
R30  0  [SM-7351-RES-0402]
R45  0  [SM-7351-RES-0402]
R46  0  [SM-7351-RES-0402]
R47  4.7K  [SM-7351-RES-0402]
R48  9.1K  [SM-7351-RES-0402]
R49  0  [SM-7351-RES-0402]
R50  0  [SM-7351-RES-0402]
R57  10K  [SM-7351-RES-0402]
R59  2.2K  [sm-7351-res-0402]
R64  0  [SM-7351-RES-0402]
R268  49.9  [SM-7351-RES-0402]
R289  10K  [SM-7351-RES-0402]
R290  0  [SM-7351-RES-0402]
R291  12K, 1%  [SM-7351-RES-0402]
R308  4.7K  [SM-7351-RES-0402]
U3  FT2232HL  [LQFP64pin]
U6  SN74AVC2T244  [son2x1-8-16m]
U7  SN74AVC4T245  [U_16_PW]
U11  SN74AVC2T244  [son2x1-8-16m]
U12  SN74LVC2G07  [U_6_DCK]  (sections A,B)
U13  SN74LVC1G00DCK  [SC70-5-43M]
U14  93LC56B  [SOIC8_MC]
U44  TPD2E001  [U_5_DRL]
U46  TPS79333  [U_5_DBV]
Y1  12MHz  [SM_OSC_ABM3]

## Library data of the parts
C9 C64 C101 C108 C115 C127 C253 C289 C329 C334 C341 C372 C375 C384 C386 C387 C400 C401 C403 C404 C408 C409 = 1C_0.1uFCapacitor16V10%0402
C1-C4 C10-C12 C16 C26 C29-C33 C40 C42 C52 C53 C68 C116 C222-C224 C235 C236 C240 C243 C255 C257 C259 C260 C280 C281 C283 C284 C290 C293 C295 C297 C300 C306 C308 C313 C314 C316 C317 C369-C371 C374 C377-C379 C410 C423 C427-C429 = 1C_0.01uFCapacitor16V10%0402
C5 C230 C261 C273 C279 C285 C291 C338 C376 C383 C388 C391 C405 C424 = 1C_10uFCapacitor16V10%0805
J4 J9 J37 = 2C_Conn_DSUB9M_TH
R8-R26 R30 R45 R46 R49-R51 R64 R100 R101 R103 R105 R153 R158 R182-R184 R186 R188 R199-R201 R203 R207 R211 R213 R221 R224 R227 R228 R272-R282 R287 R290 R318 R324 R325 R329 R331 R332 R334 R336 R338-R341 R345 R347-R349 R358 R398 R400 R405 R406 R426 R428 R435 R442 R443 R458 R459 = 1R_ZeroOhmResistor1_16W0402
U19 = 1A_MAX3232E
C237 C242 C380 C382 C407 C414 C416 C417 = 1C_0.1uFCapacitor50V10%0402
C248 C251 = 1C_47uFCapacitor16V20%1206
FB1 FB12 FB20 = 1L_FerBead_180ohm200mA
J14 J16 = 2C_Conn_3.5mm_SJ3524SMT
R3 R283 R306 R408 = 1R_ZeroOhmResistor1_16W0603
R4 R6 R52 R57 R60 R185 R187 R198 R210 R214 R225 R232 R271 R288 R289 R407 R471 R491 = 1R_10KOhmResistor1_16W0402
U24 = 1A_SN74LVC1G125
U7 U8 U37 U67 = 1A_SN74AVC4T245
U68 = 1A_TLV320AIC3106
Y5 = 1Y_Oscillator_12MHz
A1 = 4P_LCD_WVGA_7in_wCapTouchOSD
C34 C241 C396 C399 C406 C411 = 1C_1uFCapacitor10V10%0402
C249 = 1C_6.8pFCapacitor50V10%SMD0402
C250 C252 C412 = 1C_22uFCapacitor16V10%0805
C258 C335 C342 = 1C_0.001uFCapacitor50V5%0402
C265 = 1C_2200pFCapacitor50V10%SMD0402
C266-C269 C274 = 1C_0.22uFCapacitor50V10%0603
C381 = 1C_4.7uFCapacitor50V20%0805
C35 C298 C309 C389 C395 = 1C_4.7uFCapacitor16V10%0603
C390 = 47nFCapacitor16V10%0402
D5 = 1E_Diode1A20V_Schottky
D6 = Diode200mA30V_Schottky
J15 = 2C_Conn_FPC_0.5mmpitch_50posbot
J17 = 2C_Conn_FPC_527450897
L3 = 1L_4.7uHInductor20%450mAsmd
L12 = 1L_4.7uHInductor30%1.7Asmd
M19 M20 = 2M_AM43xxEVM_7inLCDMntBracket
Q3 = 1Q_MOSFET_NChan_BSS138
Q5 = 1Q_NPN_FMMT458
R192 = 1R_442Kohm1_16W1%smd0402
R193 = 1R_60.4Kohm1_16W1%smd0402
R194 R238 = 1R_499Kohm1_16W1%smd0402
R197 = 1R_357Kohm1_10W1%smd0402
R204 = 1R_49.9KOhmResistor1_16W0402
R208 = 1R_680Kohm1_16W1%smd0402
R220 = 1R_15Kohm1_16W1%smd0402
R229 = 1R_100KOhmResistor1_16W0402
R419 = 1R_2OhmResistor1_10W1%0603
R420 = 1R_10ohm1_16W5%smd0402
R421 = 1R_71.5Kohm1_10W1%smd0402
R59 R216 R218 R422 = 1R_2.2KOhmResistor1_16W0402
U26 = 1A_SN74LVC32244
U15 U27 U29 = 1A_SN74AVC8T245
U28 = 1A_SN74LVC244A
U30 U35 = 1A_SN74LVC1G04
U38 = 1A_TPS65105PWP
U42 = 1A_SN74LVC1G07
U69 = 1A_TPS61081DRC
D8 = Diode200mA250V
FB11 FB23 FB24 = 1L_FerriteBead_300ohm500mA
J19 = 2C_Conn_HDMI_TypeA
R5 R27 R47 R233 R308 R487 R488 = 1R_4.7KOhmResistor1_16W0402
R234 = 1R_10KOhmResistor1_10W1%0402
R240 = 1R_51Kohm1_16W1%smd0402
R447 = 1R_4.3KOhmResistor1_16W0402
TP24 = 2H_TestPointThroughHole
U40 = 1A_SIL9022A
U43 = 1A_TPD12S016
U72 = TPS71712
U73 = 1A_SN74LVC1G08DCKT_SC70
A2 = 4P_CameraModuleOV2659_2Mp
C282 C296 C325 C331 = 1C_2.2uFCapacitor6.3V10%smd0603
C286 C326 = 1C_15pFCapacitor50V10%smd0402
J2 = 2C_Conn_FPC_AXK_24pin
R284 R310 = 1R_30.1Kohm1_16W1%smd0402
R285 = 1R_6.8Kohm1_10W1%smd0402
R312 = 1R_39Kohm1_16W5%smd0402
TP18 TP19 = 2H_Testpoint_SMD1mmCircle
U47 = 1A_TXS0102
U48 U54 = 1A_TPS79301
U50 = 1A_SN74AVC1T45
J3 = 2H_Header12x2
PCB2 = 4P_CameraBoardAssembledPCB
J22 = 2H_Header10x2
C38 C264 C278 C385 = 1C_3.3uFCapacitor16V10%0603
C238 C239 C322 C323 = 1C_100pFCapacitor16V10%0402
R28 R202 = 1R_120ohm1_16W1%smd0402
R177 R178 R295 R296 = 1R_33ohmResistor1_16W5%0402
U2 U36 = 1A_PSM712
U9 U70 = 1A_IsoReg5V_R1Z-3.305HP
U10 U31 = 1A_ISO1050
U59 = am437x_zdn_GPEVM
C19 C25 = 1C_18pFCapacitor16V10%0402
C287 = 1C_2.2uF16V10%SMD0805
D17 = 1F_LED_Green
FB13-FB15 = 1L_FerriteBead_220ohm2A
J21 = 2C_MicroUSBAB
R48 = 1R_9.1KohmResistor1_16W1%0402
R268 = 1R_49.9OhmResistor1_16W0402
R291 = 1R_12Kohm1_16W1%SMD0402
U3 = 1A_FT2232_2
U6 U11 = 1A_SN74AVC2T244
U12 = 1A_SN74LVC2G07
U13 = 1A_SN74LVC1G00DCK
U14 = 1A_93C56EEPROM2Kbit
U44 = 1A_TPD2E001DRL
U46 = 1A_TPS79333
Y1 = 1Y_Crystal12MHzABM3

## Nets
AGND_AUD: C380.2 C382.2 C383.2 C384.2 C386.2 C387.2 C388.2 C391.2 J14.1(P1) J16.1(P1) R408.2(P2) U68.15(AVSS_ADC) U68.20(DRVSS) U68.21(DRVSS) U68.26(AVSS_DAC) U68.TPAD
AGND_CAM0: C1.2 C5.2 J2.1 R3.2(P2)
AVDD10_FB: C249.2 R192.1(P1) R193.1 U38.1(FB1)
AVDD10_IND: D5.2(ANODE) L3.2 U38.5(SW1) U38.6(SW2)
DGND: C2.2 C3.2 C4.2 C10.2 C11.2 C12.2 C16.2 C19.2 C25.2 C26.2 C29.2 C30.2 C31.2 C32.2 C33.2 C34.2 C35.2 C38.2 C40.2 C42.2 C52.1 C53.1 C64.2 C68.2 C101.2 C116.2 C127.2 C222.2 C223.2 C224.2 C230.2 C235.2 C236.2 C238.2 C239.2 C240.2 C241.2 C243.2 C250.2 C252.2 C255.2 C257.2 C258.2 C259.2 C260.2 C261.2 C266.2 C269.2 C273.2 C274.2 C279.2 C280.2 C281.2 C282.2 C283.2 C284.2 C285.2 C287.2 C289.2 C290.2 C291.2 C293.2 C295.2 C296.2 C297.2 C298.1 C300.1 C306.2 C308.1 C309.1 C313.2 C314.2 C316.2 C317.1 C322.2 C323.2 C325.2 C329.2 C331.2 C338.2 C369.2 C370.2 C371.2 C372.2 C374.2 C375.2 C376.2 C377.2 C378.2 C379.2 C381.2 C385.2 C389.2 C390.2 C395.2 C396.2 C399.2 C400.2 C401.2 C403.2 C404.2 C405.2 C406.2 C407.2 C408.2 C409.2 C410.2 C411.2 C412.2 C414.2 C416.2 C417.2 C423.2 C424.2 C427.2 C428.2 C429.2 D6.2(CATHODE) FB12.2 J2.5 J2.7 J3.11 J3.12 J3.21 J9.5 J9.10 J9.11 J15.5 J15.36 J15.38 J15.48 J15.MNT1 J15.MNT2 J17.7 J17.MNT1 J17.MNT2 J19.2(DAT2_S) J19.5(DAT1_S) J19.8(DAT0_S) J19.11(CLK_S) J19.17(DDC/CEC_GND) J19.MTG1 J19.MTG2 J19.MTG3 J19.MTG4 J21.5(GND) Q3.S(SOURCE) R3.1(P1) R4.1(P1) R18.1(P1) R48.1(P1) R60.1(P1) R158.1(P1) R182.2(P2) R184.2(P2) R193.2 R197.2 R204.1(P1) R220.2(P2) R234.1 R272.1(P1) R284.1(P1) R291.2(P2) R308.1(P1) R310.1(P1) R407.1(P1) R408.1(P1) R419.1 R421.1(P1) R422.1(P1) R426.1(P1) R435.1(P1) R447.1(P1) R471.1(P1) R491.1(P1) U3.1(GND.1) U3.5(GND.2) U3.10(AGND) U3.11(GND.3) U3.13(TEST) U3.15(GND.4) U3.25(GND.5) U3.35(GND.6) U3.47(GND.7) U3.51(GND.8) U6.5(GND) U7.8(GND) U7.9(GND) U8.3(2DIR) U8.8(GND) U8.9(GND) U9.1(VIN-) U10.4(GND1) U11.5(GND) U12.2(GND) U12.3(2A) U13.3(GND) U14.5(VSS) U14.7(NC1) U15.2(DIR) U15.11(GND) U15.12(GND) U15.13(GND) U19.15(GND) U24.3(GND) U26.B3(GND1) U26.B4(GND16) U26.D3(GND2) U26.D4(GND15) U26.E3(GND3) U26.E4(GND14) U26.G3(GND4) U26.G4(GND13) U26.K3(GND5) U26.K4(GND12) U26.M3(GND6) U26.M4(GND11) U26.N3(GND7) U26.N4(GND10) U26.R3(GND8) U26.R4(GND9) U27.2(DIR) U27.11(GND) U27.12(GND) U27.13(GND) U28.E1(GND) U29.2(DIR) U29.11(GND) U29.12(GND) U29.13(GND) U30.3(GND) U31.4(GND1) U35.3(GND) U37.8(GND) U37.9(GND) U38.7(PGND) U38.8(PGND) U38.15(C2-/MODE) U38.19(GND) U38.TP(THERM_GND) U40.43(CGND) U40.55(RSVDL) U40.57(IOGND) U40.63(AGND) U40.70(VDDQ) U40.EPAD U42.3(GND) U43.6(GND) U43.14(GND) U43.19(GND) U44.4(GND) U46.2(GND) U47.2(GND) U48.2(GND) U50.2(GND) U50.5(DIR) U54.2(GND) U67.2(1DIR) U67.8(GND) U67.9(GND) U68.42(DVSS) U68.43(SELECT) U69.4(GND) U69.8(PGND) U69.PAD(TPAD) U70.1(VIN-) U72.2(GND) U73.3(GND) Y5.2(GND) ; also on sheet 11 12 14 15 16 17 18 19 20 21 22 23 24 25 26 27
GND_CAN0: C9.2 C278.2 J4.3 J4.5 J4.6 J4.10 J4.11 U2.3 U9.4(VOUT-) U9.5(VOUT-) U10.5(GND2)
GND_CAN1: C253.2 C264.2 J37.3 J37.5 J37.6 J37.10 J37.11 U31.5(GND2) U36.3 U70.4(VOUT-) U70.5(VOUT-)
GNDA_ADC: J22.11 J22.12 R325.2(P2) R331.2(P2) ; also on sheet 18
GNDUSBJ: FB12.1 J21.S1 J21.S2 J21.S3 J21.S4
V1_2D: C405.1 C411.1 C412.1 FB23.2 FB24.2 U72.5(OUT)
V1_2D_EN: R443.1(P1) U72.3(EN)
V1_5D: C2.1 C279.1 J2.9 R283.1(P1)
V1_5D_EN: R287.1(P1) U48.3(EN)
V1_5D_FB: C286.2 R284.2(P2) R285.1(P1) U48.5(FB)
V1_5D_OUT: C282.1 C286.1 R283.2(P2) R285.2(P2) U48.6(OUT)
V1_8D: C222.1 C224.1 C375.1 C376.1 J22.1 U27.23(VCCB) U27.24(VCCB) U29.23(VCCB) U29.24(VCCB) U68.36(DVDD) ; also on sheet 18 20 21 22 25
V1_8FTDI: C10.1 C30.1 C35.1 C297.1 U3.12(VCORE.1) U3.37(VCORE.2) U3.49(VREGOUT) U3.64(VCORE.3)
V2_8A: C1.1 C5.1 FB1.1 J2.3
V2_8D: C3.1 C12.1 C40.1 C285.1 C293.1 C313.1 FB1.2 J2.12 R5.2(P2) R27.2(P2) R271.2(P2) R306.1(P1) U8.16(VCCB) U15.23(VCCB) U15.24(VCCB) U47.3(VCCA) U50.6(VCCB)
V2_8D_EN: R318.1(P1) U54.3(EN)
V2_8D_FB: C326.2 R310.2(P2) R312.1(P1) U54.5(FB)
V2_8D_OUT: C325.1 C326.1 R306.2(P2) R312.2(P2) U54.6(OUT)
V3_3AUD: C383.1 C384.1 C386.1 C387.1 C388.1 C391.1 FB20.2 U68.16(DRVDD) U68.17(DRVDD) U68.24(DRVDD) U68.25(AVDD_DAC)
V3_3D: C26.1 C29.1 C32.1 C33.1 C38.1 C42.1 C52.2 C53.2 C68.1 C116.1 C223.1 C230.1 C235.1 C236.1 C240.1 C243.1 C255.1 C257.1 C259.1 C260.1 C290.1 C314.1 C338.1 C369.1 C370.1 C371.1 C372.1 C374.1 C377.1 C378.1 C379.1 C385.1 C410.1 C423.1 C424.1 C428.1 D8.2(Anode) FB11.2 FB20.1 J17.8 R6.2(P2) R52.2(P2) R187.2(P2) R198.2(P2) R216.2(P2) R218.2(P2) R225.2(P2) R232.2(P2) R233.2(P2) R287.2(P2) R288.2(P2) R318.2(P2) R406.2(P2) R407.2(P2) R443.2(P2) R459.2(P2) U6.8(VCCB) U7.16(VCCB) U8.1(VCCA) U8.2(1DIR) U9.2(VIN+) U10.1(VCC1) U11.1(VCCA) U11.3(A2) U12.5(VCC) U13.5(VCC) U15.1(VCCA) U19.16(VCC) U24.5(VCC) U26.C3(VCC) U26.C4(VCC) U26.F3(VCC) U26.F4(VCC) U26.L3(VCC) U26.L4(VCC) U26.P3(VCC) U26.P4(VCC) U27.1(VCCA) U28.A3(VCC) U29.1(VCCA) U30.5(VCC) U31.1(VCC1) U35.5(VCC) U37.1(VCCA) U37.2(1DIR) U37.3(2DIR) U37.16(VCCB) U42.5(VCC) U43.24(VCCA) U47.7(VCCB) U50.1(VCCA) U67.1(VCCA) U67.3(2DIR) U67.16(VCCB) U68.44(IOVDD) U68.45(MFP0) U68.46(MFP1) U70.2(VIN+) U73.5(VCC) Y5.4(VCC) ; also on sheet 12 14 15 16 17 18 19 20 21 22 23 24 25 27
V3_3FTDI: C11.1 C16.1 C31.1 C64.1 C283.1 C284.1 C287.1 C306.1 C316.1 C317.2 D17.2(Anode) FB14.2 FB15.2 R57.2(P2) R289.2(P2) U3.20(VCCIO.1) U3.31(VCCIO.2) U3.42(VCCIO.3) U3.50(VREGIN) U3.56(VCCIO.4) U6.1(VCCA) U7.1(VCCA) U7.2(1DIR) U7.3(2DIR) U11.8(VCCB) U14.6(NC2) U14.8(VCC) U46.5(OUT)
V5_0D: C427.1 R487.2(P2) R488.2(P2) U43.11(VCC5V) ; also on sheet 16 17 21
V5_0HDMICONN: C429.1 J19.18(+5V) U43.13(5V_OUT)
VBAT: C4.1 C252.1 C291.1 C296.1 C331.1 C389.1 C399.1 C406.1 J3.1 J22.2 L3.1 Q5.1(C) R210.2(P2) R214.1(P1) R405.2(P2) U38.4(VIN) U46.1(IN) U48.1(IN) U54.1(IN) U69.2(VIN) U72.1(IN) ; also on sheet 11 20 21 24 27
VDDA_ADC: R332.1(P1) ; also on sheet 18
VDDA_MC_ADC: R324.1(P1) ; also on sheet 18
VDDLCD_BASE: Q5.3(B) U38.3(BASE)
AM437X_AIN0: J22.3 U59.AA12(ADC0_AIN0)
AM437X_AIN1: J22.5 U59.Y12(ADC0_AIN1)
AM437X_AIN2: J22.7 U59.Y13(ADC0_AIN2)
AM437X_AIN3: J22.9 U59.AA13(ADC0_AIN3)
AM437X_AIN4: J22.4 U59.AB13(ADC0_AIN4)
AM437X_AIN5: J22.6 U59.AC13(ADC0_AIN5)
AM437X_AIN6: J22.8 U59.AD13(ADC0_AIN6)
AM437X_AIN7: J22.10 U59.AE13(ADC0_AIN7) ; also on sheet 21
AM437X_CAM0_DATA0: R336.2(P2) U59.AE18(CAM0_DATA0)
AM437X_CAM0_DATA1: R100.2(P2) U59.AB18(CAM0_DATA1)
AM437X_CAM0_DATA2: R103.2(P2) U59.Y18(CAM0_DATA2)
AM437X_CAM0_DATA3: R101.2(P2) U59.AA18(CAM0_DATA3)
AM437X_CAM0_DATA4: R340.2(P2) U59.AE19(CAM0_DATA4)
AM437X_CAM0_DATA5: R339.2(P2) U59.AD19(CAM0_DATA5)
AM437X_CAM0_DATA6: R348.2(P2) U59.AE20(CAM0_DATA6)
AM437X_CAM0_DATA7: R345.2(P2) U59.AD20(CAM0_DATA7)
AM437X_CAM0_DATA8: TP19.1 U59.AB19(CAM0_DATA8)
AM437X_CAM0_DATA9: TP18.1 U59.AA19(CAM0_DATA9)
AM437X_CAM0_HSYNC: R329.2(P2) U59.AE17(CAM0_HSYNC)
AM437X_CAM0_PCLK: R105.2(P2) U59.AC20(CAM0_PCLK)
AM437X_CAM0_VSYNC: R334.2(P2) U59.AD18(CAM0_VSYNC)
AM437X_CAM1_DATA0: R281.2(P2) U59.AB20(CAM1_DATA0)
AM437X_CAM1_DATA1: R9.2(P2) U59.AC21(CAM1_DATA1)
AM437X_CAM1_DATA2: R11.2(P2) U59.AD21(CAM1_DATA2)
AM437X_CAM1_DATA3: R14.2(P2) U59.AE22(CAM1_DATA3)
AM437X_CAM1_DATA4: R15.2(P2) U59.AD22(CAM1_DATA4)
AM437X_CAM1_DATA5: R276.2(P2) U59.AE23(CAM1_DATA5)
AM437X_CAM1_DATA6: R280.1(P1) U59.AD23(CAM1_DATA6)
AM437X_CAM1_DATA7: R10.1(P1) U59.AE24(CAM1_DATA7)
AM437X_CAM1_DATA8: R12.1(P1) U59.AD24(CAM1_DATA8)
AM437X_CAM1_DATA9: R279.1(P1) U59.AC24(CAM1_DATA9)
AM437X_CAM1_HSYNC: R8.1(P1) U59.AD25(CAM1_HSYNC)
AM437X_CAM1_PCLK: R13.2(P2) U59.AE21(CAM1_PCLK)
AM437X_CAM1_VSYNC: R282.1(P1) U59.AC23(CAM1_VSYNC)
AM437X_CLKOUT1: R358.2(P2) U59.D24(XDMA_EVENT_INTR0/CLKOUT1)
AM437X_DCAN0_RX: C323.1 R296.1 U59.L22(UART1_RTSN/DCAN0_RX)
AM437X_DCAN0_TX: R295.1 U59.K22(UART1_CTSN/DCAN0_TX)
AM437X_DCAN1_RX: C239.1 R178.1 U59.L21(UART1_TXD/DCAN1_RX)
AM437X_DCAN1_TX: R177.1 U59.K21(UART1_RXD/DCAN1_TX)
AM437X_HDMI_INTn: R228.2(P2) ; also on sheet 24
AM437X_LCD_AC_BIAS_EN: U28.B2(2A4) U28.D1(1A4) U59.A24(DSS_AC_BIAS_EN) ; also on sheet 14
AM437X_LCD_DATA0: U26.A5(1A1) U26.J5(5A1) U59.B22(DSS_DATA0) ; also on sheet 14
AM437X_LCD_DATA1: U26.A6(1A2) U26.J6(5A2) U59.A21(DSS_DATA1) ; also on sheet 14
AM437X_LCD_DATA2: U26.B5(1A3) U26.K5(5A3) U59.B21(DSS_DATA2) ; also on sheet 14
AM437X_LCD_DATA3: U26.B6(1A4) U26.K6(5A4) U59.C21(DSS_DATA3) ; also on sheet 14
AM437X_LCD_DATA4: U26.C5(2A1) U26.L5(6A1) U59.A20(DSS_DATA4) ; also on sheet 14
AM437X_LCD_DATA5: U26.C6(2A2) U26.L6(6A2) U59.B20(DSS_DATA5) ; also on sheet 14
AM437X_LCD_DATA6: U26.D5(2A3) U26.M5(6A3) U59.C20(DSS_DATA6) ; also on sheet 14
AM437X_LCD_DATA7: U26.D6(2A4) U26.M6(6A4) U59.E19(DSS_DATA7) ; also on sheet 14
AM437X_LCD_DATA8: U26.E5(3A1) U26.N5(7A1) U59.A19(DSS_DATA8) ; also on sheet 14
AM437X_LCD_DATA9: U26.E6(3A2) U26.N6(7A2) U59.B19(DSS_DATA9) ; also on sheet 14
AM437X_LCD_DATA10: U26.F5(3A3) U26.P5(7A3) U59.A18(DSS_DATA10) ; also on sheet 14
AM437X_LCD_DATA11: U26.F6(3A4) U26.P6(7A4) U59.B18(DSS_DATA11) ; also on sheet 14
AM437X_LCD_DATA12: U26.G5(4A1) U26.R5(8A1) U59.C19(DSS_DATA12) ; also on sheet 14
AM437X_LCD_DATA13: U26.G6(4A2) U26.R6(8A2) U59.D19(DSS_DATA13) ; also on sheet 14
AM437X_LCD_DATA14: U26.H5(4A3) U26.T5(8A3) U59.C17(DSS_DATA14) ; also on sheet 14
AM437X_LCD_DATA15: U26.H6(4A4) U26.T6(8A4) U59.D17(DSS_DATA15) ; also on sheet 14
AM437X_LCD_DATA16: U27.21(B1) U29.21(B1) U59.A11(GPMC_AD15/DSS_DATA16)
AM437X_LCD_DATA17: U27.20(B2) U29.20(B2) U59.B11(GPMC_AD14/DSS_DATA17)
AM437X_LCD_DATA18: U27.19(B3) U29.19(B3) U59.C11(GPMC_AD13/DSS_DATA18)
AM437X_LCD_DATA19: U27.18(B4) U29.18(B4) U59.E11(GPMC_AD12/DSS_DATA19)
AM437X_LCD_DATA20: U27.17(B5) U29.17(B5) U59.D11(GPMC_AD11/DSS_DATA20)
AM437X_LCD_DATA21: U27.16(B6) U29.16(B6) U59.F11(GPMC_AD10/DSS_DATA21)
AM437X_LCD_DATA22: U27.15(B7) U29.15(B7) U59.A10(GPMC_AD9/DSS_DATA22)
AM437X_LCD_DATA23: U27.14(B8) U29.14(B8) U59.B10(GPMC_AD8/DSS_DATA23)
AM437X_LCD_HSYNC: U28.B1(1A2) U28.D2(2A2) U59.A23(DSS_HSYNC) ; also on sheet 14
AM437X_LCD_PCLK: U28.A1(1A1) U28.E3(2A1) U59.A22(DSS_PCLK)
AM437X_LCD_VSYNC: U28.C1(1A3) U28.C3(2A3) U59.B23(DSS_VSYNC) ; also on sheet 14
AM437X_MAG_ADC0: J22.13 U59.AC16(ADC1_AIN0)
AM437X_MAG_ADC1: J22.15 U59.AB16(ADC1_AIN1)
AM437X_MAG_ADC2: J22.17 U59.AA16(ADC1_AIN2)
AM437X_MAG_ADC3: J22.19 U59.AB15(ADC1_AIN3)
AM437X_MAG_ADC4: J22.14 U59.AA15(ADC1_AIN4)
AM437X_MAG_ADC5: J22.16 U59.Y15(ADC1_AIN5)
AM437X_MAG_ADC6: J22.18 U59.AE16(ADC1_AIN6)
AM437X_MAG_ADC7: J22.20 U59.AD16(ADC1_AIN7)
AM437X_MCASP1_AXR3: R491.2(P2) U24.4(Y) U59.A16(RMII1_REFCLK/MCASP1_AXR3)
AM437X_STATUS_LED1: R46.1(P1) ; also on sheet 11 24
AM437X_STATUS_LED2: R45.1(P1) ; also on sheet 11 24
AM437X_VREFN: C341.2 C342.2 R331.1(P1) U59.AE14(ADC0_VREFN)
AM437X_VREFP: C341.1 C342.1 R332.2(P2) U59.AD14(ADC0_VREFP)
AUD_HPLOUT: C248.1 U68.18(HPLOUT)
AUD_HPLOUT_JCK: C248.2 J16.2(P2)
AUD_HPROUT: C251.1 U68.23(HPROUT)
AUD_HPROUT_JCK: C251.2 J16.3(P3)
AUD_LINEINL: C237.1 U68.3(LINE1LP)
AUD_LINEINL_JCK: C237.2 J14.2(P2)
AUD_LINEINR: C242.1 U68.5(LINE1RP)
AUD_LINEINR_JCK: C242.2 J14.3(P3)
AUD_RESETn: R400.1(P1) U68.33(RESETn)
AUDIO_MSTRCLK: R17.2(P2) R51.2(P2) R153.1(P1) R358.1(P1) U37.7(2A2) U67.7(2A2)
BKLT_EN: Q3.G(GATE) R187.1(P1) R188.1(P1)
BKLT_L: L12.1 U69.1(L)
BKLT_SW: L12.2 U69.10(SW)
CAM0_DATA0: R336.1(P1) U15.3(A1)
CAM0_DATA1: R100.1(P1) U15.4(A2)
CAM0_DATA2: R103.1(P1) U15.5(A3)
CAM0_DATA3: R101.1(P1) U15.6(A4)
CAM0_DATA4: R340.1(P1) U15.7(A5)
CAM0_DATA5: R339.1(P1) U15.8(A6)
CAM0_DATA6: R348.1(P1) U15.9(A7)
CAM0_DATA7: R345.1(P1) U15.10(A8)
CAM0_GIO0: C34.1 R52.1(P1) U8.5(1A2)
CAM0_HSYNC: R329.1(P1) U8.7(2A2)
CAM0_PCLK: R105.1(P1) U50.3(A)
CAM0_SRCCLK: R51.1(P1) U8.4(1A1)
CAM0_VSYNC: R334.1(P1) U8.6(2A1)
CAM1_DATA0: J3.3 R281.1(P1)
CAM1_DATA1: J3.5 R9.1(P1)
CAM1_DATA2: J3.7 R11.1(P1)
CAM1_DATA3: J3.13 R14.1(P1)
CAM1_DATA4: J3.15 R15.1(P1)
CAM1_DATA5: J3.17 R276.1(P1)
CAM1_DATA6: J3.6 R280.2(P2)
CAM1_DATA7: J3.8 R10.2(P2)
CAM1_DATA8: J3.10 R12.2(P2)
CAM1_DATA9: J3.14 R279.2(P2)
CAM1_FIELD: J3.20 R275.2(P2)
CAM1_GIO0: J3.16 R278.2(P2)
CAM1_GIO1: J3.18 R277.2(P2)
CAM1_HSYNC: J3.4 R8.2(P2)
CAM1_PCLK: J3.9 R13.1(P1)
CAM1_SRCCLK: J3.23 R17.1(P1)
CAM1_VSYNC: J3.2 R282.2(P2)
CAM1_WEN: J3.19 R16.1(P1)
CAN0_H: J4.7 R28.2(P2) U2.1 U10.7(CANH)
CAN0_L: J4.2 R28.1(P1) U2.2 U10.6(CANL)
CAN0_RXDF: R296.2 U10.2(RXD)
CAN0_TXDF: C322.1 R295.2 U10.3(TXD)
CAN1_H: J37.7 R202.2(P2) U31.7(CANH) U36.1
CAN1_L: J37.2 R202.1(P1) U31.6(CANL) U36.2
CAN1_RXDF: R178.2 U31.2(RXD)
CAN1_TXDF: C238.1 R177.2 U31.3(TXD)
COMP: C265.2 U38.22(COMP)
COMP_CAP: C265.1 R220.1(P1)
EECS: U3.63(EECS) U14.1(CS)
EEDATA: R59.1(P1) U3.61(EEDATA) U14.3(DI)
EESK: U3.62(EESK) U14.2(CLK)
EMU_USB_DM: J21.2(DM) U3.7(DM) U44.3(IO1)
EMU_USB_DP: J21.3(DP) U3.8(DP) U44.5(IO2)
F_ADBUS0: R30.2(P2) U3.16(ADBUS0)
F_ADBUS1: R26.2(P2) U3.17(ADBUS1)
F_ADBUS2: R25.2(P2) U3.18(ADBUS2)
F_ADBUS3: R24.2(P2) U3.19(ADBUS3)
F_ADBUS4: R23.2(P2) U3.21(ADBUS4)
F_ADBUS5: R21.2(P2) U3.26(ACBUS0)
F_ADBUS6: R22.2(P2) U3.23(ADBUS6)
F_ADBUS7: R19.2(P2) U3.30(ACBUS4)
FT_SRESET: R21.1(P1) R308.2(P2) U13.1(A)
FT_SRESETB: R64.2(P2) U12.6(1Y)
FT_SRESETn: U12.1(1A) U13.4(Y)
FT_VBUS: R49.1(P1) U13.2(B)
FTDI_REF: R291.1(P1) U3.6(REF)
FTDI_XTIN: C25.1 U3.2(XTIN) Y1.1
FTDI_XTOUT: C19.1 U3.3(XTOUT) Y1.2
GP_I2C_SCL: R201.1(P1) R227.2(P2) U47.8(B1) U68.1(SCL) ; also on sheet 21 24 27
GP_I2C_SDA: R200.1(P1) R224.2(P2) U47.1(B2) U68.2(SDA) ; also on sheet 21 24 27
HDMI_AUDBCLK: R213.1(P1) U40.45(SCK)
HDMI_AUDD0: R428.1(P1) U40.41(SD0)
HDMI_AUDFSX: R211.1(P1) U40.44(WS)
HDMI_AUDMCLK: R207.1(P1) U40.38(MCLK)
HDMI_CEC: R240.1(P1) U40.71(CEC_A) U43.1(CEC_A)
HDMI_CEC_D: R221.2(P2) U40.50(CEC_D)
HDMI_CLK+: J19.10(CLK+) U40.59(TXC+) U43.16(TMDS_CK+)
HDMI_CLK-: J19.12(CLK-) U40.58(TXC-) U43.15(TMDS_CK-)
HDMI_CT_HPD: R458.2(P2) R459.1(P1) U43.12(CT_HPD)
HDMI_D0: U26.J2(5Y1) U40.32(VDATA_IN0)
HDMI_D1: U26.J1(5Y2) U40.31(VDATA_IN1)
HDMI_D2: U26.K2(5Y3) U40.30(VDATA_IN2)
HDMI_D3: U26.K1(5Y4) U40.29(VDATA_IN3)
HDMI_D4: U26.L2(6Y1) U40.28(VDATA_IN4)
HDMI_D5: U26.L1(6Y2) U40.27(VDATA_IN5)
HDMI_D6: U26.M2(6Y3) U40.25(VDATA_IN6)
HDMI_D7: U26.M1(6Y4) U40.24(VDATA_IN7)
HDMI_D8: U26.N2(7Y1) U40.23(VDATA_IN8)
HDMI_D9: U26.N1(7Y2) U40.20(VDATA_IN9)
HDMI_D10: U26.P2(7Y3) U40.19(VDATA_IN10)
HDMI_D11: U26.P1(7Y4) U40.18(VDATA_IN11)
HDMI_D12: U26.R2(8Y1) U40.17(VDATA_IN12)
HDMI_D13: U26.R1(8Y2) U40.16(VDATA_IN13)
HDMI_D14: U26.T2(8Y3) U40.15(VDATA_IN14)
HDMI_D15: U26.T1(8Y4) U40.14(VDATA_IN15)
HDMI_D16: U27.3(A1) U40.13(VDATA_IN16)
HDMI_D17: U27.4(A2) U40.11(VDATA_IN17)
HDMI_D18: U27.5(A3) U40.10(VDATA_IN18)
HDMI_D19: U27.6(A4) U40.9(VDATA_IN19)
HDMI_D20: U27.7(A5) U40.8(VDATA_IN20)
HDMI_D21: U27.8(A6) U40.7(VDATA_IN21)
HDMI_D22: U27.9(A7) U40.6(VDATA_IN22)
HDMI_D23: U27.10(A8) U40.4(VDATA_IN23)
HDMI_DE: U28.B3(2Y4) U40.33(DE)
HDMI_EXTSWING: R447.2(P2) U40.56(EXT_SWING)
HDMI_HPLG: R234.2 U40.54(HPD) U43.4(HPD_A)
HDMI_HSYNC: U28.D3(2Y2) U40.34(HSYNC)
HDMI_I2C_SCL: R227.1(P1) U40.1(CSCL)
HDMI_I2C_SDA: R224.1(P1) U40.2(CSDA)
HDMI_I2CSCL: R218.1(P1) U40.49(DSCL) U43.2(SCL_A)
HDMI_I2CSDA: R216.1(P1) U40.48(DSDA) U43.3(SDA_A)
HDMI_INTn: R225.1(P1) R228.1(P1) U40.52(INT)
HDMI_LSOE: R458.1(P1) U43.5(LS_OE)
HDMI_PCLK: U28.E2(2Y1) U40.22(IDCK)
HDMI_TX0+: J19.7(DAT0+) U40.62(TX0+) U43.18(TMDS_D0+)
HDMI_TX0-: J19.9(DAT0-) U40.61(TX0-) U43.17(TMDS_D0-)
HDMI_TX1+: J19.4(DAT1+) U40.65(TX1+) U43.21(TMDS_D1+)
HDMI_TX1-: J19.6(DAT1-) U40.64(TX1-) U43.20(TMDS_D1-)
HDMI_TX2+: J19.1(DAT2+) U40.68(TX2+) U43.23(TMDS_D2+)
HDMI_TX2-: J19.3(DAT2-) U40.67(TX2-) U43.22(TMDS_D2-)
HDMI_VSYNC: U28.C2(2Y3) U40.35(VSYNC)
HDMICONN_CEC: J19.13(CEC) U43.7(CEC_B)
HDMICONN_HPLG: J19.19(HPLG) R471.2(P2) U43.10(HPD_B)
HDMICONN_I2CSCL: J19.15(SCL) R487.1(P1) U43.8(SCL_B)
HDMICONN_I2CSDA: J19.16(SDA) R488.1(P1) U43.9(SDA_B)
I2C0_SCL: R274.1(P1) ; also on sheet 14 21
I2C0_SDA: R273.1(P1) ; also on sheet 14 21
JTAG_TCK: U7.13(1B1) ; also on sheet 14
JTAG_TDI: U7.12(1B2) ; also on sheet 14
JTAG_TDO: U11.2(A1) ; also on sheet 14
JTAG_TMS: U7.11(2B1) ; also on sheet 14
JTAG_TRSTn: U7.10(2B2) ; also on sheet 14
JTAGPOD_PRES: R50.1(P1) ; also on sheet 14
LCD_AVDD_EN: R210.1(P1) U38.24(EN)
LCD_BACKLIGHT: R188.2(P2) U59.G24(ECAP0_IN_PWM0_OUT)
LCD_BLUE0: J15.19 U26.A2(1Y1)
LCD_BLUE1: J15.18 U26.A1(1Y2)
LCD_BLUE2: J15.17 U26.B2(1Y3)
LCD_BLUE3: J15.16 U26.B1(1Y4)
LCD_BLUE4: J15.15 U26.C2(2Y1)
LCD_BLUE5: J15.14 U26.C1(2Y2)
LCD_BLUE6: J15.13 U26.D2(2Y3)
LCD_BLUE7: J15.12 U26.D1(2Y4)
LCD_DITHER: J15.47 R186.1(P1)
LCD_EN: J15.9 U28.E4(1Y4)
LCD_GREEN0: J15.27 U26.E2(3Y1)
LCD_GREEN1: J15.26 U26.E1(3Y2)
LCD_GREEN2: J15.25 U26.F2(3Y3)
LCD_GREEN3: J15.24 U26.F1(3Y4)
LCD_GREEN4: J15.23 U26.G2(4Y1)
LCD_GREEN5: J15.22 U26.G1(4Y2)
LCD_GREEN6: J15.21 U26.H2(4Y3)
LCD_GREEN7: J15.20 U26.H1(4Y4)
LCD_HSYNC: J15.11 U28.C4(1Y2)
LCD_LEFTRIGHT: J15.39 R183.1(P1)
LCD_PCLK: J15.37 U28.B4(1Y1)
LCD_RED0: J15.35 U29.3(A1)
LCD_RED1: J15.34 U29.4(A2)
LCD_RED2: J15.33 U29.5(A3)
LCD_RED3: J15.32 U29.6(A4)
LCD_RED4: J15.31 U29.7(A5)
LCD_RED5: J15.30 U29.8(A6)
LCD_RED6: J15.29 U29.9(A7)
LCD_RED7: J15.28 U29.10(A8)
LCD_RESETn: C241.1 J15.44 R185.1(P1)
LCD_UPDOWN: J15.40 R184.1(P1)
LCD_VSYNC: J15.10 U28.D4(1Y3)
LOWPOWERn: U73.1(A) ; also on sheet 24
LOWPWR_RSTn: R400.2(P2) R442.2(P2) U73.4(Y)
MCASP1_ACLKX: U37.4(1A1) U59.B14(GMII1_CRS/MCASP1_ACLKX) U67.4(1A1)
MCASP1_AXR2: U37.6(2A1) U59.D16(GMII1_COL/MCASP1_AXR2) U67.6(2A1)
MCASP1_FSX: U37.5(1A2) U59.B13(GMII1_RXERR/MCASP1_FSX) U67.5(1A2)
RS232_0CTS: J9.8 U19.8(RIN2)
RS232_0RTS: J9.7 U19.7(DOUT2)
RS232_0RXD: J9.2 U19.13(RIN1)
RS232_0TXD: J9.3 U19.14(DOUT1)
SEL_LCDn: R398.1(P1) U26.A3(1~{OE}) U26.A4(2~{OE}) U26.H3(4~{OE}) U26.H4(3~{OE}) U28.A2(1OE#) U29.22(~{OE}) U30.4(Y)
SEL_LCDORHDMIn: R203.1(P1) R232.1(P1) U26.J3(5~{OE}) U26.J4(6~{OE}) U26.T3(8~{OE}) U26.T4(7~{OE}) U27.22(~{OE}) U28.A4(2OE#) U30.2(A) U42.2(A) ; also on sheet 24
SENSOR_HREF: J2.8 U8.10(2B2)
SENSOR_PCLK: J2.13 U50.4(B)
SENSOR_PWRDN: J2.11 R271.1(P1) R272.2(P2)
SENSOR_RESET: J2.15 U8.12(1B2)
SENSOR_SIO_C: J2.4 R5.1(P1) U47.5(A1)
SENSOR_SIO_D: J2.2 R27.1(P1) U47.4(A2)
SENSOR_VSYNC: J2.6 U8.11(2B1)
SENSOR_XCLK: J2.10 U8.13(1B1)
SENSOR_Y2: J2.24 U15.21(B1)
SENSOR_Y3: J2.23 U15.20(B2)
SENSOR_Y4: J2.22 U15.19(B3)
SENSOR_Y5: J2.21 U15.18(B4)
SENSOR_Y6: J2.20 U15.17(B5)
SENSOR_Y7: J2.19 U15.16(B6)
SENSOR_Y8: J2.18 U15.15(B7)
SENSOR_Y9: J2.17 U15.14(B8)
SYS_RESETn: R64.1(P1) U35.2(A) U73.2(B) ; also on sheet 14 15 22
TOUCH_INTn: R199.1(P1) ; also on sheet 24
TSC_RESETn: J17.6 R422.2(P2) U35.4(Y)
UART0_CTSn: R338.1(P1) U19.9(ROUT2)
UART0_RTSn: R341.1(P1) U19.10(DIN2)
UART0_RXD: R349.1(P1) U19.12(ROUT1)
UART0_TXD: R347.1(P1) U19.11(DIN1)
USBJTAG_ENn: R50.2(P2) U6.4(~{OE}) U7.14(2~{OE}) U7.15(1~{OE}) U11.4(~{OE})
VCAN0: C9.1 C278.1 J4.9 U9.7(VOUT+) U10.8(VCC2)
VCAN1: C253.1 C264.1 J37.9 U31.8(VCC2) U70.7(VOUT+)
VCOMC+: C267.2 U38.16(C1+)
VCOMC-: C267.1 U38.17(C1-)
VCOMIN: C258.1 R194.1(P1) R197.1 U38.11(VCOMIN)
VFTDI_PHY: C308.2 C309.2 FB15.1 U3.4(VPHY)
VFTDI_PLL: C298.2 C300.2 FB14.1 U3.9(VPLL)
VGHFB: R204.2(P2) R208.1(P1) U38.12(FB3)
VGL_DRV: C268.2 U38.18(DRV)
VGL_FB: R229.2(P2) R238.1(P1) U38.21(FB2)
VGL_REF: C269.1 R229.1(P1) U38.20(REF)
VHDMI_AVCC12: C261.1 C416.1 C417.1 FB23.1 U40.60(AVCC12) U40.66(AVCC12)
VHDMI_CVCC12: C400.1 C401.1 C403.1 C404.1 C408.1 C409.1 FB24.1 U40.5(CVCC12) U40.12(CVCC12) U40.26(CVCC12) U40.42(CVCC12) U40.47(CVCC12) U40.53(CVCC12)
VHDMI_IOVCC: C273.1 C407.1 C414.1 FB11.1 U40.3(IOVCC) U40.21(IOVCC) U40.46(IOVCC)
VLCD_AVDD: C249.1 C250.1 D5.1(CATHODE) J15.43 R192.2(P2) R194.2(P2) U38.9(SUPP)
VLCD_DVDD: C395.1 J15.7 Q5.2(E) R183.2(P2) R185.2(P2) R186.2(P2) U38.2(FB4)
VLCD_VCOM: C396.1 J15.6 J15.46 U38.10(VCOM)
VLCD_VGH: C266.1 J15.41 R208.2(P2) U38.13(OUT3)
VLCD_VGL: C274.1 D6.1(ANODE) J15.42 R238.2(P2)
VLED+: C381.1 J15.1 J15.2 U69.9(OUT)
VLED-: J15.3 J15.4 R419.2 U69.5(FB)
VUSB_FTDI: C281.1 FB13.2 R47.2(P2) R290.1(P1)
VUSB_JTAG: C280.1 FB13.1 J21.1(VBUS) U44.1(VCC)
N10547354: R406.1(P1) U69.6(EN)
N10547358: C390.1 R420.2(P2) R421.2(P2) U69.3(SS)
N10547410: Q3.D(DRAIN) R420.1(P1)
N10547584: R405.1(P1) U69.7(FSW)
N10899547: R214.2(P2) U38.23(ENR) U42.4(Y)
N10900827: C268.1 D6.3(CATHANOD)
N10937487: C101.1 U19.6(V-)
N10937491: C127.1 U19.2(V+)
N10937507: C115.2 U19.3(C1-)
N10937511: C108.1 U19.4(C2+)
N10937515: C108.2 U19.5(C2-)
N10937529: C115.1 U19.1(C1+)
N10937893: R347.2(P2) U59.J24(UART0_TXD)
N10937905: R341.2(P2) U59.J25(UART0_RTSn)
N10937909: R349.2(P2) U59.K25(UART0_RXD)
N10937921: R338.2(P2) U59.L25(UART0_CTSn)
N12433526: R442.1(P1) U40.51(RESETn)
N12433674: R233.1(P1) U40.72(CI2CA)
N12433889: R426.2(P2) U40.36(SPDIF)
N12434699: R435.2(P2) U40.69(IO_SEL)
N12434935: D8.1(Cathode) R240.2(P2)
N12435159: R221.1(P1) TP24.1
N12957779: R20.2(P2) U3.28(ACBUS2)
N12957783: R4.2(P2) R20.1(P1) U11.6(B2)
N12957791: R18.2(P2) U3.32(ACBUS5)
N12957851: R47.1(P1) R48.2(P2) R49.2(P2) U3.59(BCBUS7)
N12958009: R289.1(P1) U3.14(RESET#)
N12958129: D17.1(Cathode) R268.1(P1)
N12958219: R57.1(P1) R59.2(P2) U14.4(DO)
N12958347: R268.2(P2) U3.60(PWREN#)
N12958943: R25.1(P1) U11.7(B1)
N12959041: R290.2(P2) U46.3(EN)
N12959089: C295.1 U46.4(NR)
N15198290: C382.1 U68.6(LINE1RM)
N15198329: C380.1 U68.4(LINE1LM)
N15592722: J3.22 R274.2(P2)
N15592726: J3.24 R273.2(P2)
N16423861: R6.1(P1) R278.1(P1)
N17104819: R158.2(P2) Y5.1(OE)
N17208812: J15.8 R182.1(P1)
N17283795: C334.2 C335.2 R325.1(P1) U59.AD15(ADC1_VREFN)
N17283801: C334.1 C335.1 R324.2(P2) U59.AE15(ADC1_VREFP)
N17511082: R22.1(P1) U6.2(A1)
N17511110: R19.1(P1) U6.3(A2)
N17512123: R30.1(P1) U7.4(1A1)
N17512125: R26.1(P1) U7.5(1A2)
N17512127: R24.1(P1) U7.6(2A1)
N17512129: R23.1(P1) U7.7(2A2)
N17517305: R153.2(P2) Y5.3(CLK)
N17517963: R398.2(P2) U24.1(~{OE}) U67.14(2~{OE}) U67.15(1~{OE})
N17518729: R207.2(P2) U37.10(2B2)
N17518739: R428.2(P2) U37.11(2B1)
N17518741: R213.2(P2) U37.13(1B1)
N17518743: R211.2(P2) U37.12(1B2)
N17518767: R203.2(P2) U37.14(2~{OE}) U37.15(1~{OE})
N17546871: U67.13(1B1) U68.38(BCLK)
N17546880: U67.12(1B2) U68.39(WCLK)
N17546889: U67.10(2B2) U68.37(MCLK)
N17547178: U67.11(2B1) U68.40(DIN)
N17547363: U24.2(A) U68.41(DOUT)
N17571259: R60.2(P2) U8.14(2~{OE}) U8.15(1~{OE}) U15.22(~{OE})
N17572398: R288.1(P1) U47.6(OE)
N17573016: C289.1 U48.4(NR)
N17573154: C329.1 U54.4(NR)
N17638051: R46.2(P2) U6.7(B1)
N17638054: R45.2(P2) U6.6(B2)
N17769726: J17.5 R201.2(P2)
N17769728: J17.4 R200.2(P2)
N17769730: J17.3 R198.1(P1) R199.2(P2)

Not connected (* = marked no-connect by the designer): J2 14* 16*; J4 1* 4* 8; J9 1* 4* 6* 9*; J14 10(P10)*; J15 45 49 50; J16 10(P10)*; J17 1 2; J19 14(NC)*; J21 4(ID)*; J37 1* 4* 8; R16 2(P2)*; R275 1(P1)*; R277 1(P1)*; U3 22(ADBUS5)* 24(ADBUS7)* 27(ACBUS1)* 29(ACBUS3)* 33(ACBUS6)* 34(ACBUS7)* 36(SUSPEND#) 38(BDBUS0)* 39(BDBUS1)* 40(BDBUS2)* 41(BDBUS3)* 43(BDBUS4)* 44(BDBUS5)* 45(BDBUS6)* 46(BDBUS7)* 48(BCBUS0)* 52(BCBUS1)* 53(BCBUS2)* 54(BCBUS3)* 55(BCBUS4)* 57(BCBUS5)* 58(BCBUS6)*; U9 10(NC); U12 4(2Y)*; U30 1(NC)*; U35 1(NC)*; U38 14(C2+); U40 37(SD3)* 39(SD2)* 40(SD1)*; U42 1(NC)*; U44 2(NC)*; U68 7(LINE2LP)* 8(LINE2LM)* 9(LINE2RP)* 10(LINE2RM)* 11(MIC3L)* 12(MICDET)* 13(MICBIAS)* 14(MIC3R)* 19(HPLCOM)* 22(HPRCOM)* 27(MONO_LOP)* 28(MONO_LOM)* 29(LEFT_LOP)* 30(LEFT_LOM)* 31(RIGHT_ROP)* 32(RIGHT_ROM)* 34(GPIO2)* 35(GPIO1)* 47(MFP2)* 48(MFP3)*; U70 10(NC); U72 4(NR)*

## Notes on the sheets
sheet 2
- UART #0 RS-232
sheet 5
- BackLight Power
sheet 6
- Audio
  Headphone Out
- Audio
  Line in
sheet 10
- USB JTAG
